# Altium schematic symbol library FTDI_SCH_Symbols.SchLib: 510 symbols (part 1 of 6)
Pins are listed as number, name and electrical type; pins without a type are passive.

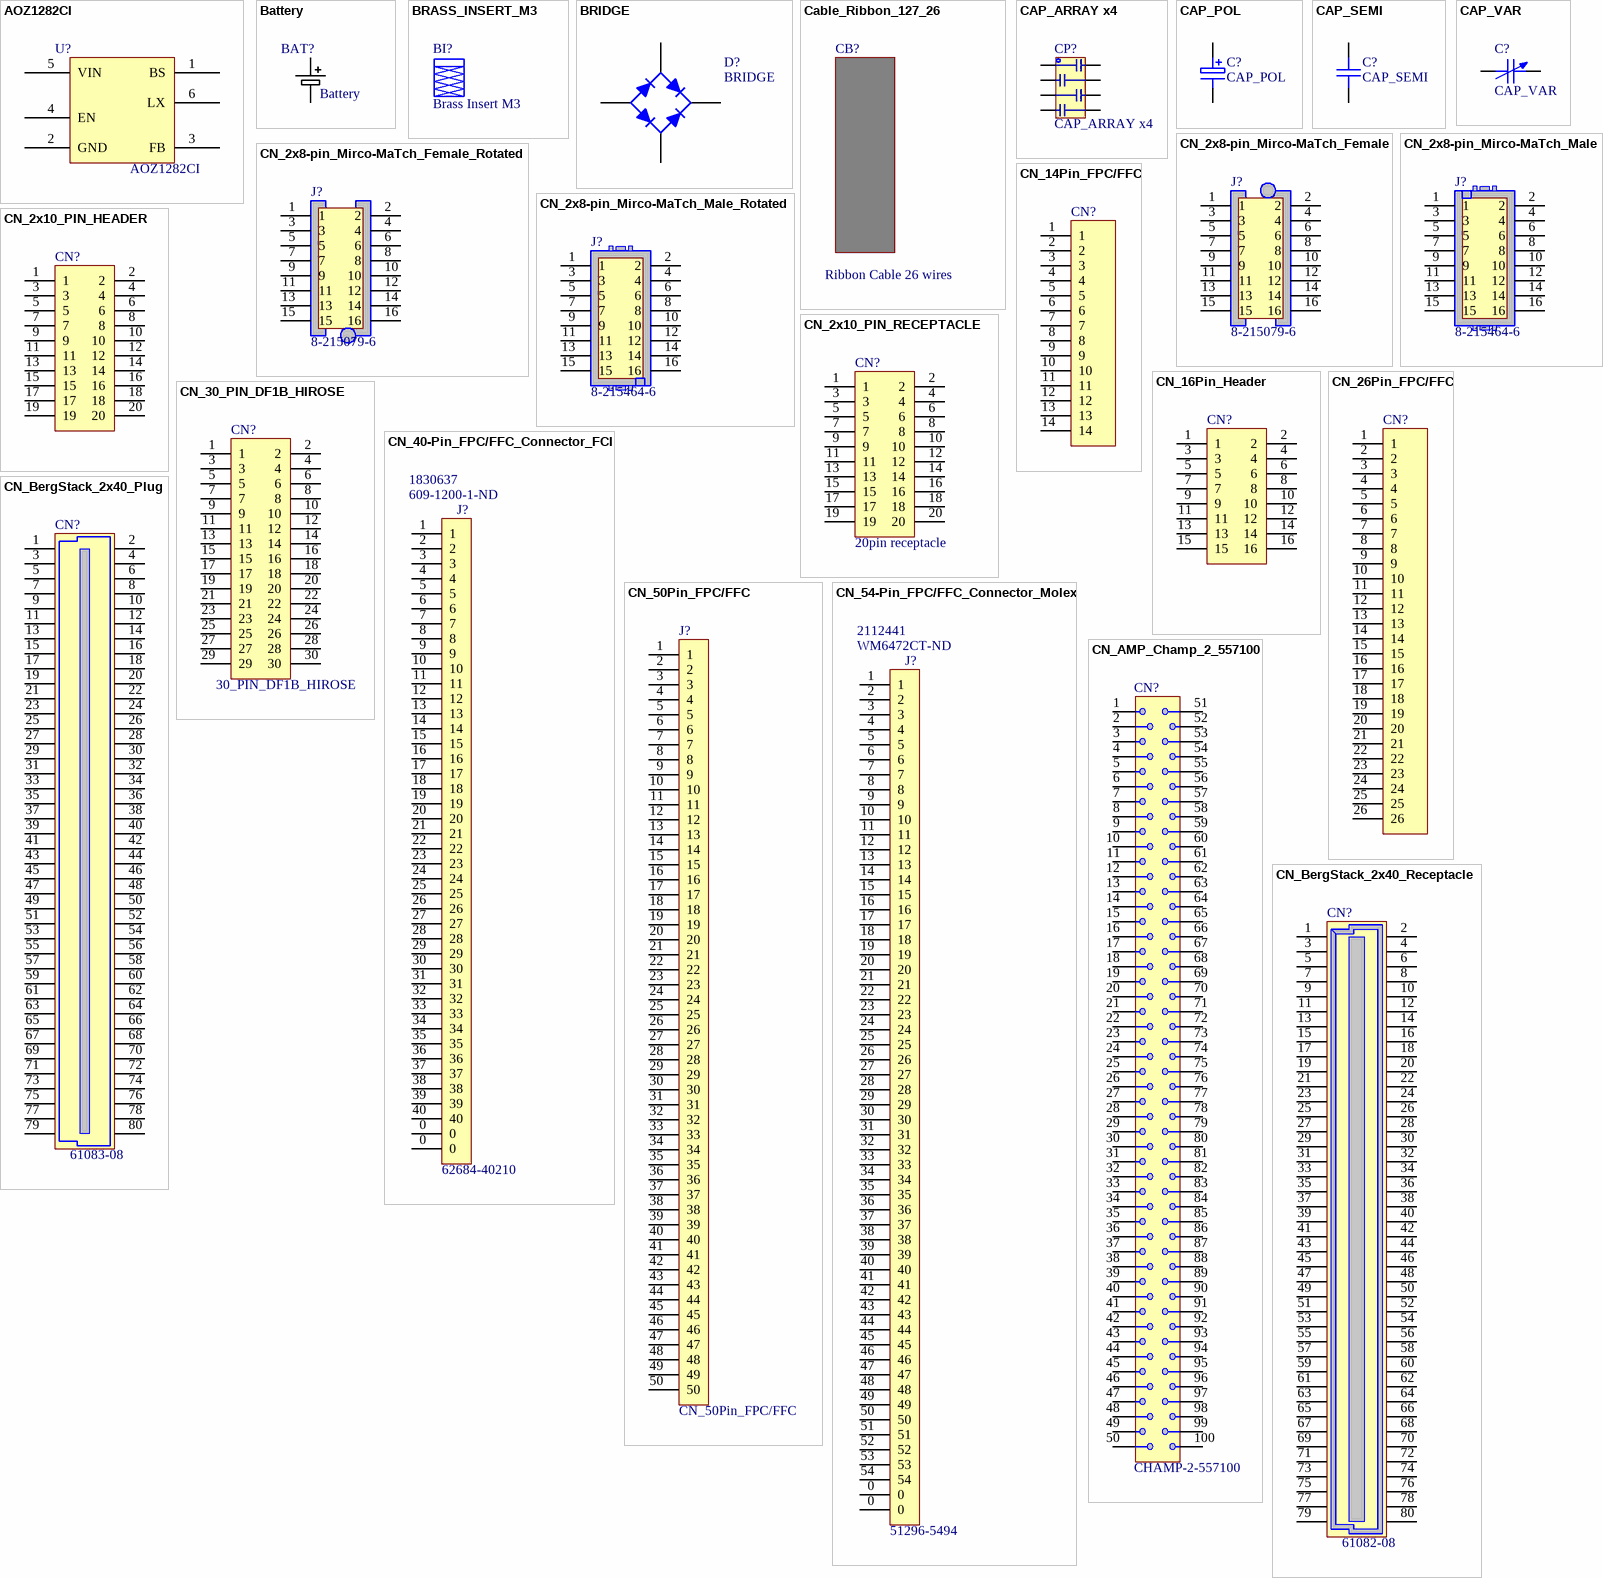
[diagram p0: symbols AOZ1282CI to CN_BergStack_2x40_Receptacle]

## AOZ1282CI
designator U?
pins: 1 BS, 2 GND, 3 FB, 4 EN, 5 VIN (power), 6 LX

## Battery
designator BAT?
pins: 1 +, 2 -

## BRASS_INSERT_M3
designator BI?, comment Brass Insert M3  (mechanical)

## BRIDGE
designator D?
Full Wave Diode Bridge
footprint D-38 (Bridge Rectifier; 4 Terminals; Body 9.4 x 9.4 mm (typ); Pitch 5.08 mm)
simulation model BRIDGE (Spice Subcircuit)
pins: 1 A, 2 C, 3 K, 4 C

## Cable_Ribbon_127_26
designator CB?, comment Ribbon Cable 26 wires  (mechanical)
Ribbon cable, 26-wires, 1.27mm pitch

## CAP_ARRAY x4
designator CP?
Capacitor array 3216 x 4
footprint MNR34 (3216x4 Resistor Array)
footprint RESARRAY-EXBV8V (EXBV8 Series Resistor Array, 4x0603, Isolated; Panasonic)
footprint RES_ARRAY_4X0603
pins: 1, 2, 3, 4, 5, 6, 7, 8

## CAP_POL
designator C?
Polarized Capacitor
simulation model CAP (Capacitor)
signal-integrity model Cap Pol
footprint CAPE-CASE A (Capacitor aluminium electrolitytic; SMT, Case A)
footprint CAPE-CASE B (Capacitor, aluminium electrolitytic; SMT, Case B)
footprint CAPE-4mm (Capacitor, aluminium electrolitytic; DIA 4mm; Pitch 1.5mm)
footprint CAPM-A-3216-18 (Capacitor, SMT Tantalum; Body 3.2 x 1.6 mm (LxW typ))
footprint CAPM-B-3528-21 (Capacitor, SMT Tantalum; Body 3.5 x 2.8 mm (LxW typ))
footprint CAPM-C-6032-28 (Capacitor, SMT, Tantalum; Body 6.0 x 3.2 mm (LxW typ))
footprint CAPM-D-7343-31 (Capacitor, SMT, Tantalum; Body 7.3 x 4.3 mm (LxW typ))
footprint CAPE-5mm (Capacitor, aluminium electrolitytic; DIA 5mm; Pitch 2mm)
footprint CAPE-6.3mm (Capacitor, aluminium electrolitytic; DIA 6,3mm; Pitch 2.5mm)
footprint CAPE-CASE C (Capacitor, aluminium electrolitytic; SMT, Case C)
pins: 1, 2
1 alternate drawing of the same symbol

## CAP_SEMI
designator C?
Capacitor bipolar
simulation model CAP (Semiconductor Capacitor)
signal-integrity model Cap Semi
footprint CAPC1608-0603 (Chip Capacitor; Body 1.6 x 0.8 mm (LxW typ))
footprint CAPC2012-0805 (Chip Capacitor; Body 2 x 1.3 mm (LxW typ))
footprint CAPC3216-1206 (Chip Capacitor; Body 3.2 x 1.6 mm (LxW typ))
footprint RAD-0.2 (Jumper Wire; 2 Leads)
pins: 1, 2

## CAP_VAR
designator C?
Variable or Adjustable Capacitor
signal-integrity model Cap Var
footprint MURATA-TZ03-TYPE-E (MURATA TRIMMER CAP TZ03 SERIES - E TYPE)
pins: 1, 2

## CN_2x8-pin_Mirco-MaTch_Female
designator J?, comment 8-215079-6
2x8-pin; Micro-MaTch; Female; On-Board Connector; TE Connectivity; 1-215079-6 (Reel Packaging) or 8-215079-6 (Box Packaging); Note: CONN FMALE-ON-BRD 16POS VERT T/H
footprint CN_16-Pin_Female_Micro-Match_1-215079-6 (Micro-MaTch Board-Board Receptacle; 16-possitions; 0.1"(2.54mm) pitch; staggered pins; TE Connectivity; 1-215079-6 (8-215079-6))
pins: 1, 2, 3, 4, 5, 6, 7, 8, 9, 10, 11, 12, 13, 14, 15, 16

## CN_2x8-pin_Mirco-MaTch_Female_Rotated
designator J?, comment 8-215079-6
2x8-pin; Micro-MaTch; Female; On-Board Connector; TE Connectivity; 1-215079-6 (Reel Packaging) or 8-215079-6 (Box Packaging); Note: CONN FMALE-ON-BRD 16POS VERT T/H
footprint CN_16-Pin_Female_Micro-Match_1-215079-6-Rotated_180_deg (Micro-MaTch Board-Board Receptacle; 16-possitions; 0.1"(2.54mm) pitch; staggered pins; TE Connectivity; 1-215079-6 (8-215079-6))
pins: 1, 2, 3, 4, 5, 6, 7, 8, 9, 10, 11, 12, 13, 14, 15, 16

## CN_2x8-pin_Mirco-MaTch_Male
designator J?, comment 8-215464-6
2x8-pin; Micro-MaTch; Male; On-Board Connector; TE Connectivity; 1-215464-6 (Reel packaging) or 8-215464-6 (Box Packaging); Note: CONN HEADER 16POS VERT DL TIN
footprint CN_16-Pins_Female_Micro-Match_8-215079-6 (Micro-MaTch Board-Board Receptacle; 16-possitions; 0.1"(2.54mm) pitch; staggered pins)
pins: 1, 2, 3, 4, 5, 6, 7, 8, 9, 10, 11, 12, 13, 14, 15, 16

## CN_2x8-pin_Mirco-MaTch_Male_Rotated
designator J?, comment 8-215464-6
2x8-pin; Micro-MaTch; Male; On-Board Connector; TE Connectivity; 1-215464-6 (Reel packaging) or 8-215464-6 (Box Packaging); Note: CONN HEADER 16POS VERT DL TIN
footprint CN_16-Pin_Male_Micro-Match_1-215464-6 - rotated (Micro-MaTch Board-Board Header; 16-possitions; 0.1"(2.54mm) pitch; staggered pins; TE Connectivity; 1-215464-6 (8-215464-6))
pins: 1, 2, 3, 4, 5, 6, 7, 8, 9, 10, 11, 12, 13, 14, 15, 16

## CN_2x10_PIN_HEADER
designator CN?
footprint CN_20_Pin_Socket
pins: 1, 2, 3, 4, 5, 6, 7, 8, 9, 10, 11, 12, 13, 14, 15, 16, 17, 18, 19, 20

## CN_2x10_PIN_RECEPTACLE
designator CN?, comment 20pin receptacle
Receptacle; 20 pin
footprint CN_20_Pin_Receptacle
pins: 1, 2, 3, 4, 5, 6, 7, 8, 9, 10, 11, 12, 13, 14, 15, 16, 17, 18, 19, 20

## CN_14Pin_FPC/FFC
designator CN?
footprint CN_16Pin_Female_Header (Dual Row; Vertical; 0.1" (2.54mm); Female Header)
footprint CN_FCI_SFW14R-1ST (FPC/FFC Connector; SFW14R-1ST; 14 Positions; 1.0mm Spaced Bottom Contact; FCI)
pins: 1, 2, 3, 4, 5, 6, 7, 8, 9, 10, 11, 12, 13, 14, 15 0 hidden, 16 0 hidden

## CN_16Pin_Header
designator CN?
footprint CN_16Pin_Female_Header (Dual Row; Vertical; 0.1" (2.54mm); Female Header)
footprint CN_16Pin_Male_Header (Dual Row; Vertical; 0.1" (2.54mm); Male Header)
pins: 1, 2, 3, 4, 5, 6, 7, 8, 9, 10, 11, 12, 13, 14, 15, 16

## CN_26Pin_FPC/FFC
designator CN?
footprint CN_16Pin_Female_Header (Dual Row; Vertical; 0.1" (2.54mm); Female Header)
footprint CN_FCI_SFW26R-1ST (FPC/FFC Connector; SFW26R-1ST; 26 Positions; 1.0mm Spaced Bottom Contact; FCI)
pins: 1, 2, 3, 4, 5, 6, 7, 8, 9, 10, 11, 12, 13, 14, 15, 16, 17, 18, 19, 20, 21, 22, 23, 24, 25, 26, 27 0 hidden, 28 0 hidden

## CN_30_PIN_DF1B_HIROSE
designator CN?, comment 30_PIN_DF1B_HIROSE
Hirose, DF1B Series, 2.5mm Pitch Connector for Discrete Wire Connection
footprint CN_DF1B-30DP-2.5DS (Hirose Double Row Right Angle Pin Header, 2.5mm pitch, Catalog number - 541-0642-4-**)
pins: 1, 2, 3, 4, 5, 6, 7, 8, 9, 10, 11, 12, 13, 14, 15, 16, 17, 18, 19, 20, 21, 22, 23, 24, 25, 26, 27, 28, 29, 30

## CN_40-Pin_FPC/FFC_Connector_FCI
designator J?, comment 62684-40210  Supplier Part Number 1: 609-1200-1-ND  Supplier Part Number 2: 1830637
40-Pin; 0.5mm pitch; FPC/FFC Connector; Top Contacts; FCI; Part No. 62684-40210
footprint CN_4-5nch_TFT (Connector for 4.3 and 5" touch screens)
pins: 0, 0, 1, 2, 3, 4, 5, 6, 7, 8, 9, 10, 11, 12, 13, 14, 15, 16, 17, 18, 19, 20, 21, 22, 23, 24, 25, 26, 27, 28, 29, 30, 31, 32, 33, 34, 35, 36, 37, 38, 39, 40

## CN_50Pin_FPC/FFC
designator J?
footprint CN_50Pin_FPC/FFC
pins: 1, 2, 3, 4, 5, 6, 7, 8, 9, 10, 11, 12, 13, 14, 15, 16, 17, 18, 19, 20, 21, 22, 23, 24, 25, 26, 27, 28, 29, 30, 31, 32, 33, 34, 35, 36, 37, 38, 39, 40, 41, 42, 43, 44, 45, 46, 47, 48, 49, 50

## CN_54-Pin_FPC/FFC_Connector_Molex
designator J?, comment 51296-5494  Supplier Part Number 1: WM6472CT-ND  Supplier Part Number 2: 2112441
54-Pin; 0.5mm pitch; FPC/FFC Connector; Bottom Contacts; Molex; Part No. 51296-5494; Manufacturer: Molex Inc; ManufacturerPartNo: 0512965494; Note: CONN FFC/FPC 54POS ZIF .5MM SMD
footprint CN_3-5nch_TFT (Connector for 3.5" touch screens)
pins: 0, 0, 1, 2, 3, 4, 5, 6, 7, 8, 9, 10, 11, 12, 13, 14, 15, 16, 17, 18, 19, 20, 21, 22, 23, 24, 25, 26, 27, 28, 29, 30, 31, 32, 33, 34, 35, 36, 37, 38, 39, 40, 41, 42, 43, 44, 45, 46, 47, 48, 49, 50, 51, 52, 53, 54

## CN_AMP_Champ_2_557100
designator CN?, comment CHAMP-2-557100
Amp Champ-2 series 100 pin connector
footprint CN_CHAMP-100 (Connector; CHAMP Miniature Ribbon 050 Series I; 100 Position; Right Angle)
pins: 1, 2, 3, 4, 5, 6, 7, 8, 9, 10, 11, 12, 13, 14, 15, 16, 17, 18, 19, 20, 21, 22, 23, 24, 25, 26, 27, 28, 29, 30, 31, 32, 33, 34, 35, 36, 37, 38, 39, 40, 41, 42, 43, 44, 45, 46, 47, 48, 49, 50, 51, 52, 53, 54, 55, 56, 57, 58, 59, 60, 61, 62, 63, 64, 65, 66, 67, 68, 69, 70, 71, 72, 73, 74, 75, 76, 77, 78, 79, 80, 81, 82, 83, 84, 85, 86, 87, 88, 89, 90, 91, 92, 93, 94, 95, 96, 97, 98, 99, 100

## CN_BergStack_2x40_Plug
designator CN?, comment 61083-08
FCI, BesrgStack family, 2x40 pins, 0.8mm pitch, Board to Board Plug
footprint CN_61083-084402LF (FCI, 2x40 pins, 0.8mm pitch, 7.7mm height, Board to Board Plug)
pins: 1, 2, 3, 4, 5, 6, 7, 8, 9, 10, 11, 12, 13, 14, 15, 16, 17, 18, 19, 20, 21, 22, 23, 24, 25, 26, 27, 28, 29, 30, 31, 32, 33, 34, 35, 36, 37, 38, 39, 40, 41, 42, 43, 44, 45, 46, 47, 48, 49, 50, 51, 52, 53, 54, 55, 56, 57, 58, 59, 60, 61, 62, 63, 64, 65, 66, 67, 68, 69, 70, 71, 72, 73, 74, 75, 76, 77, 78, 79, 80

## CN_BergStack_2x40_Receptacle
designator CN?, comment 61082-08
FCI, BesrgStack family, 2x40 pins, 0.8mm pitch, Board to Board Receptacle
footprint CN_61082-082402LF (FCI, 2x40 pins, 0.8mm pitch, 7.7mm height, Board to Board Receptacle)
pins: 1, 2, 3, 4, 5, 6, 7, 8, 9, 10, 11, 12, 13, 14, 15, 16, 17, 18, 19, 20, 21, 22, 23, 24, 25, 26, 27, 28, 29, 30, 31, 32, 33, 34, 35, 36, 37, 38, 39, 40, 41, 42, 43, 44, 45, 46, 47, 48, 49, 50, 51, 52, 53, 54, 55, 56, 57, 58, 59, 60, 61, 62, 63, 64, 65, 66, 67, 68, 69, 70, 71, 72, 73, 74, 75, 76, 77, 78, 79, 80

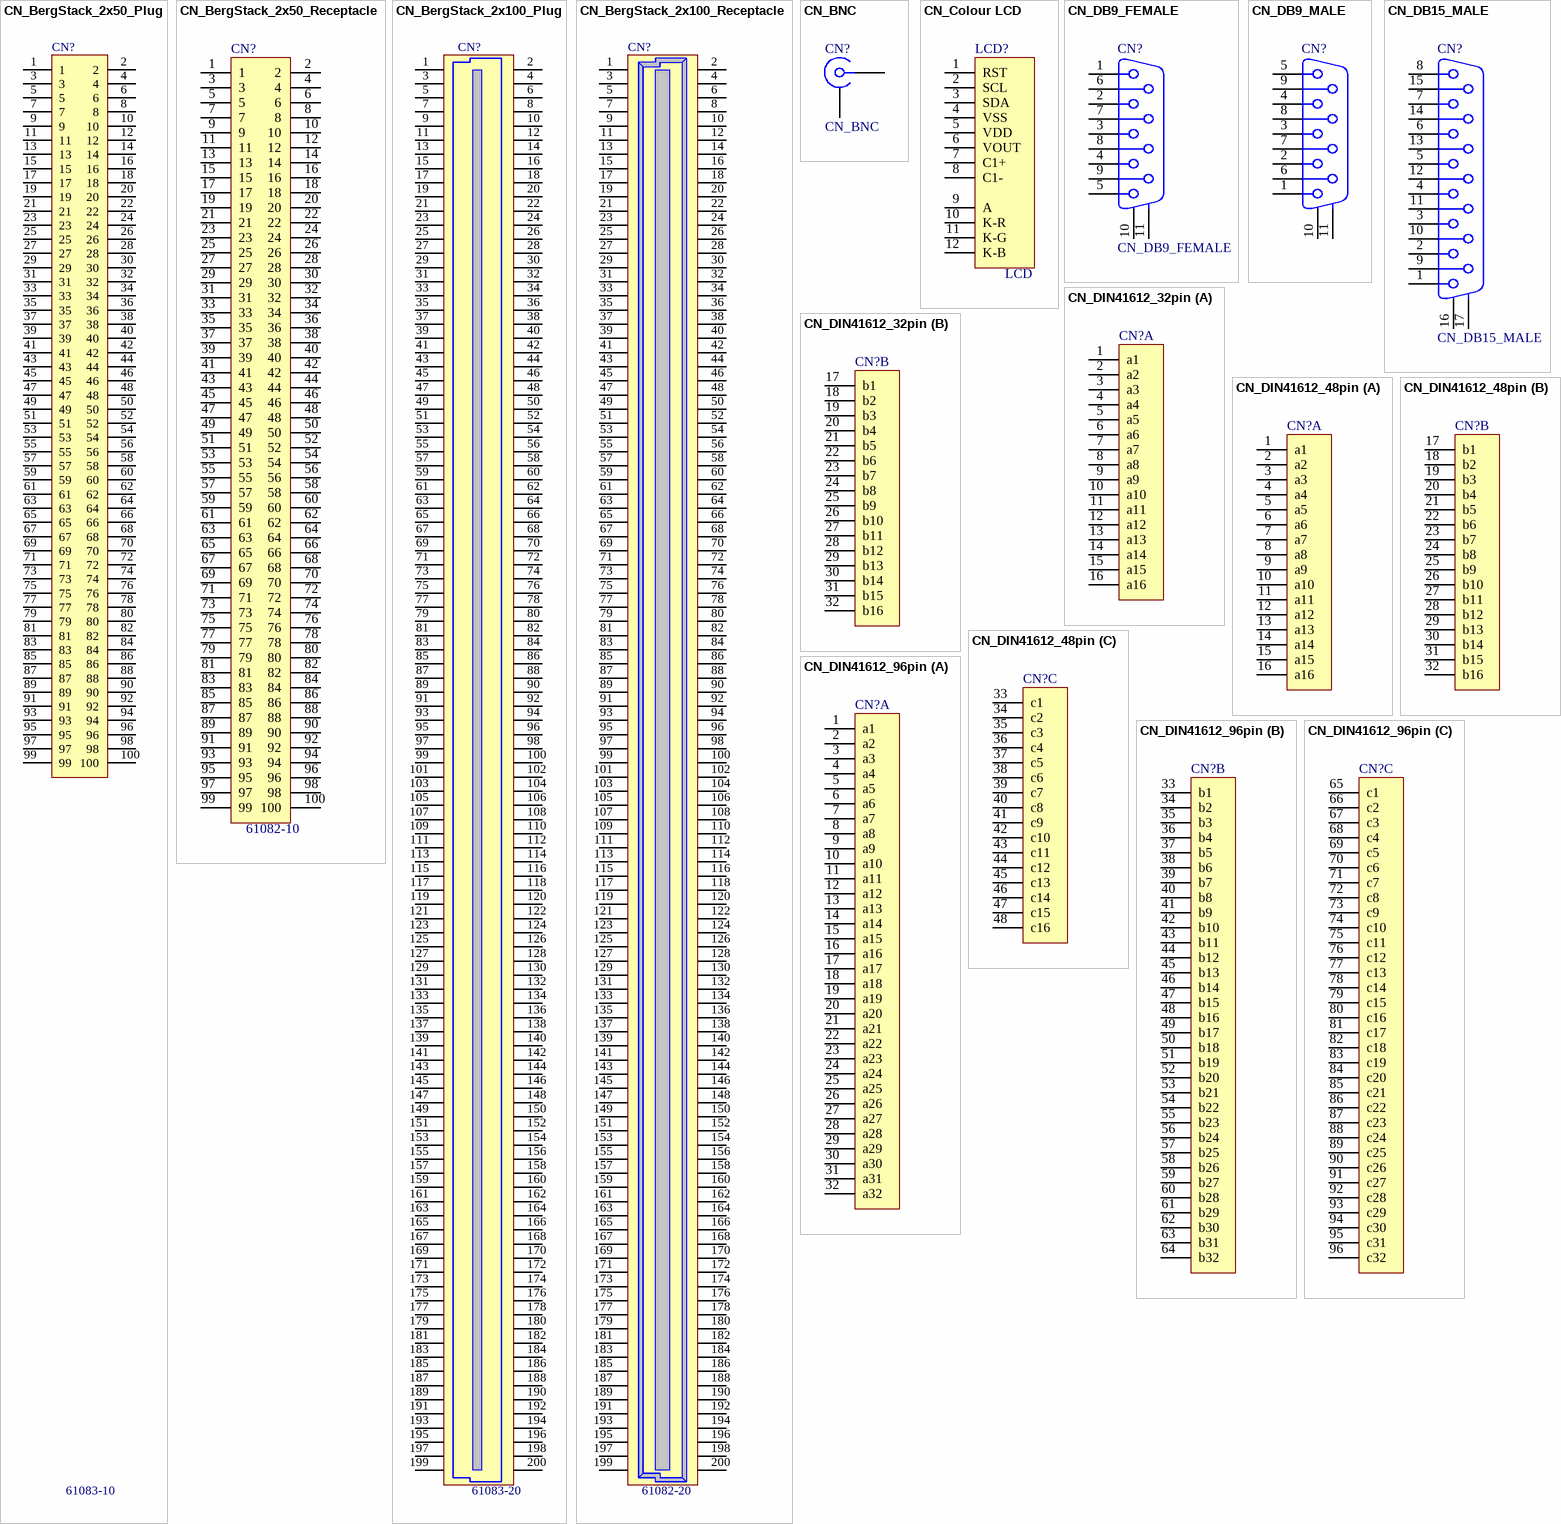
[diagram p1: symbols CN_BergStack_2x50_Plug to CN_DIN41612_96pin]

## CN_BergStack_2x50_Plug
designator CN?, comment 61083-10
FCI, BesrgStack family, 2x50 pins, 0.8mm pitch, Board to Board Plug
footprint CN_61083-104402LF (FCI, 2x50 pins, 0.8mm pitch, 7.7mm height, Board to Board Plug)
pins: 1, 2, 3, 4, 5, 6, 7, 8, 9, 10, 11, 12, 13, 14, 15, 16, 17, 18, 19, 20, 21, 22, 23, 24, 25, 26, 27, 28, 29, 30, 31, 32, 33, 34, 35, 36, 37, 38, 39, 40, 41, 42, 43, 44, 45, 46, 47, 48, 49, 50, 51, 52, 53, 54, 55, 56, 57, 58, 59, 60, 61, 62, 63, 64, 65, 66, 67, 68, 69, 70, 71, 72, 73, 74, 75, 76, 77, 78, 79, 80, 81, 82, 83, 84, 85, 86, 87, 88, 89, 90, 91, 92, 93, 94, 95, 96, 97, 98, 99, 100

## CN_BergStack_2x50_Receptacle
designator CN?, comment 61082-10
FCI, BesrgStack family, 2x50 pins, 0.8mm pitch, Board to Board Receptacle
footprint CN_61082-102402LF - duplicate (FCI, 2x50 pins, 0.8mm pitch, 7.7mm height, Board to Board Receptacle)
pins: 1, 2, 3, 4, 5, 6, 7, 8, 9, 10, 11, 12, 13, 14, 15, 16, 17, 18, 19, 20, 21, 22, 23, 24, 25, 26, 27, 28, 29, 30, 31, 32, 33, 34, 35, 36, 37, 38, 39, 40, 41, 42, 43, 44, 45, 46, 47, 48, 49, 50, 51, 52, 53, 54, 55, 56, 57, 58, 59, 60, 61, 62, 63, 64, 65, 66, 67, 68, 69, 70, 71, 72, 73, 74, 75, 76, 77, 78, 79, 80, 81, 82, 83, 84, 85, 86, 87, 88, 89, 90, 91, 92, 93, 94, 95, 96, 97, 98, 99, 100

## CN_BergStack_2x100_Plug
designator CN?, comment 61083-20
FCI, BesrgStack family, 2x100 pins, 0.8mm pitch, Board to Board Plug
footprint CN_61083-204402LF (FCI, 2x100 pins, 0.8mm pitch, 7.7mm height, Board to Board Plug)
pins: 1, 2, 3, 4, 5, 6, 7, 8, 9, 10, 11, 12, 13, 14, 15, 16, 17, 18, 19, 20, 21, 22, 23, 24, 25, 26, 27, 28, 29, 30, 31, 32, 33, 34, 35, 36, 37, 38, 39, 40, 41, 42, 43, 44, 45, 46, 47, 48, 49, 50, 51, 52, 53, 54, 55, 56, 57, 58, 59, 60, 61, 62, 63, 64, 65, 66, 67, 68, 69, 70, 71, 72, 73, 74, 75, 76, 77, 78, 79, 80, 81, 82, 83, 84, 85, 86, 87, 88, 89, 90, 91, 92, 93, 94, 95, 96, 97, 98, 99, 100, 101, 102, 103, 104, 105, 106, 107, 108, 109, 110, 111, 112, 113, 114, 115, 116, 117, 118, 119, 120, 121, 122, 123, 124, 125, 126, 127, 128, 129, 130, 131, 132, 133, 134, 135, 136, 137, 138, 139, 140, 141, 142, 143, 144, 145, 146, 147, 148, 149, 150, 151, 152, 153, 154, 155, 156, 157, 158, 159, 160, 161, 162, 163, 164, 165, 166, 167, 168, 169, 170, 171, 172, 173, 174, 175, 176, 177, 178, 179, 180, 181, 182, 183, 184, 185, 186, 187, 188, 189, 190, 191, 192, 193, 194, 195, 196, 197, 198, 199, 200

## CN_BergStack_2x100_Receptacle
designator CN?, comment 61082-20
FCI, BesrgStack family, 2x100 pins, 0.8mm pitch, Board to Board Receptacle
footprint CN_61082-202402LF (FCI, 2x100 pins, 0.8mm pitch, 7.7mm height, Board to Board Receptacle)
pins: 1, 2, 3, 4, 5, 6, 7, 8, 9, 10, 11, 12, 13, 14, 15, 16, 17, 18, 19, 20, 21, 22, 23, 24, 25, 26, 27, 28, 29, 30, 31, 32, 33, 34, 35, 36, 37, 38, 39, 40, 41, 42, 43, 44, 45, 46, 47, 48, 49, 50, 51, 52, 53, 54, 55, 56, 57, 58, 59, 60, 61, 62, 63, 64, 65, 66, 67, 68, 69, 70, 71, 72, 73, 74, 75, 76, 77, 78, 79, 80, 81, 82, 83, 84, 85, 86, 87, 88, 89, 90, 91, 92, 93, 94, 95, 96, 97, 98, 99, 100, 101, 102, 103, 104, 105, 106, 107, 108, 109, 110, 111, 112, 113, 114, 115, 116, 117, 118, 119, 120, 121, 122, 123, 124, 125, 126, 127, 128, 129, 130, 131, 132, 133, 134, 135, 136, 137, 138, 139, 140, 141, 142, 143, 144, 145, 146, 147, 148, 149, 150, 151, 152, 153, 154, 155, 156, 157, 158, 159, 160, 161, 162, 163, 164, 165, 166, 167, 168, 169, 170, 171, 172, 173, 174, 175, 176, 177, 178, 179, 180, 181, 182, 183, 184, 185, 186, 187, 188, 189, 190, 191, 192, 193, 194, 195, 196, 197, 198, 199, 200

## CN_BNC
designator CN?
footprint CN_BNC/RA
pins: 1, 2

## CN_Colour LCD
designator LCD?, comment LCD
Header, -Pin; Manufacturer: Newhaven Display Intl; ManufacturerPartNo: NHD-C0220BIZ-FS(RGB)-FBW-3VM-ND; Note: LCD DISPLAY RGB LED BKLT 20 X 2
footprint Colour LCD
signal-integrity model Connector
pins: 1 RST, 2 SCL, 3 SDA, 4 VSS, 5 VDD, 6 VOUT, 7 C1+, 8 C1-, 9 A, 10 K-R, 11 K-G, 12 K-B

## CN_DB9_FEMALE
designator CN?
Connector; D-Sub; 9 pin; Female
signal-integrity model Connector
footprint CN_DSUB-9_FEMALE (Connector; D Subminiature AMPLIMITE 2000; 9 Position; Right Angle)
pins: 1, 2, 3, 4, 5, 6, 7, 8, 9, 10 MH1, 11 MH2

## CN_DB9_MALE
designator CN?
Connector D-Sub; 9 Position; Male
signal-integrity model Connector
footprint CN_DSUB-9_MALE (Connector; D Subminiature AMPLIMITE 2000; 9 Position; Right Angle)
pins: 1, 2, 3, 4, 5, 6, 7, 8, 9, 10 MH1, 11 MH2

## CN_DB15_MALE
designator CN?
Socket; D-Sub;, 15 Position, Right Angle; Male
signal-integrity model Connector
footprint CN_DSUB-15_MALE (Connector; D Subminiature AMPLIMITE 2000; 15 Position; Right Angle)
pins: 1, 2, 3, 4, 5, 6, 7, 8, 9, 10, 11, 12, 13, 14, 15, 16 MH1, 17 MH2

## CN_DIN41612_32pin
designator CN?
footprint CN_DIN41612_32Pin_Female (Connector DIN41612; 32 pin; Female; horizontal)
part A pins: 1 a1, 2 a2, 3 a3, 4 a4, 5 a5, 6 a6, 7 a7, 8 a8, 9 a9, 10 a10, 11 a11, 12 a12, 13 a13, 14 a14, 15 a15, 16 a16
part B pins: 17 b1, 18 b2, 19 b3, 20 b4, 21 b5, 22 b6, 23 b7, 24 b8, 25 b9, 26 b10, 27 b11, 28 b12, 29 b13, 30 b14, 31 b15, 32 b16

## CN_DIN41612_48pin
designator CN?
footprint CN_DIN41612_48 pin Male (DIN41612 series; Harting Part No. 09 28 148 6903 ; Number of Positions = 48; pitch 2.54 mm)
part A pins: 1 a1, 2 a2, 3 a3, 4 a4, 5 a5, 6 a6, 7 a7, 8 a8, 9 a9, 10 a10, 11 a11, 12 a12, 13 a13, 14 a14, 15 a15, 16 a16
part B pins: 17 b1, 18 b2, 19 b3, 20 b4, 21 b5, 22 b6, 23 b7, 24 b8, 25 b9, 26 b10, 27 b11, 28 b12, 29 b13, 30 b14, 31 b15, 32 b16
part C pins: 33 c1, 34 c2, 35 c3, 36 c4, 37 c5, 38 c6, 39 c7, 40 c8, 41 c9, 42 c10, 43 c11, 44 c12, 45 c13, 46 c14, 47 c15, 48 c16

## CN_DIN41612_96pin
designator CN?
footprint CN_DIN41612_96 pin Male (DIN41612 series; FCI Part No. 86093967113745E1LF; Number of Positions = 95; pitch 2.54 mm)
part A pins: 1 a1, 2 a2, 3 a3, 4 a4, 5 a5, 6 a6, 7 a7, 8 a8, 9 a9, 10 a10, 11 a11, 12 a12, 13 a13, 14 a14, 15 a15, 16 a16, 17 a17, 18 a18, 19 a19, 20 a20, 21 a21, 22 a22, 23 a23, 24 a24, 25 a25, 26 a26, 27 a27, 28 a28, 29 a29, 30 a30, 31 a31, 32 a32
part B pins: 33 b1, 34 b2, 35 b3, 36 b4, 37 b5, 38 b6, 39 b7, 40 b8, 41 b9, 42 b10, 43 b11, 44 b12, 45 b13, 46 b14, 47 b15, 48 b16, 49 b17, 50 b18, 51 b19, 52 b20, 53 b21, 54 b22, 55 b23, 56 b24, 57 b25, 58 b26, 59 b27, 60 b28, 61 b29, 62 b30, 63 b31, 64 b32
part C pins: 65 c1, 66 c2, 67 c3, 68 c4, 69 c5, 70 c6, 71 c7, 72 c8, 73 c9, 74 c10, 75 c11, 76 c12, 77 c13, 78 c14, 79 c15, 80 c16, 81 c17, 82 c18, 83 c19, 84 c20, 85 c21, 86 c22, 87 c23, 88 c24, 89 c25, 90 c26, 91 c27, 92 c28, 93 c29, 94 c30, 95 c31, 96 c32

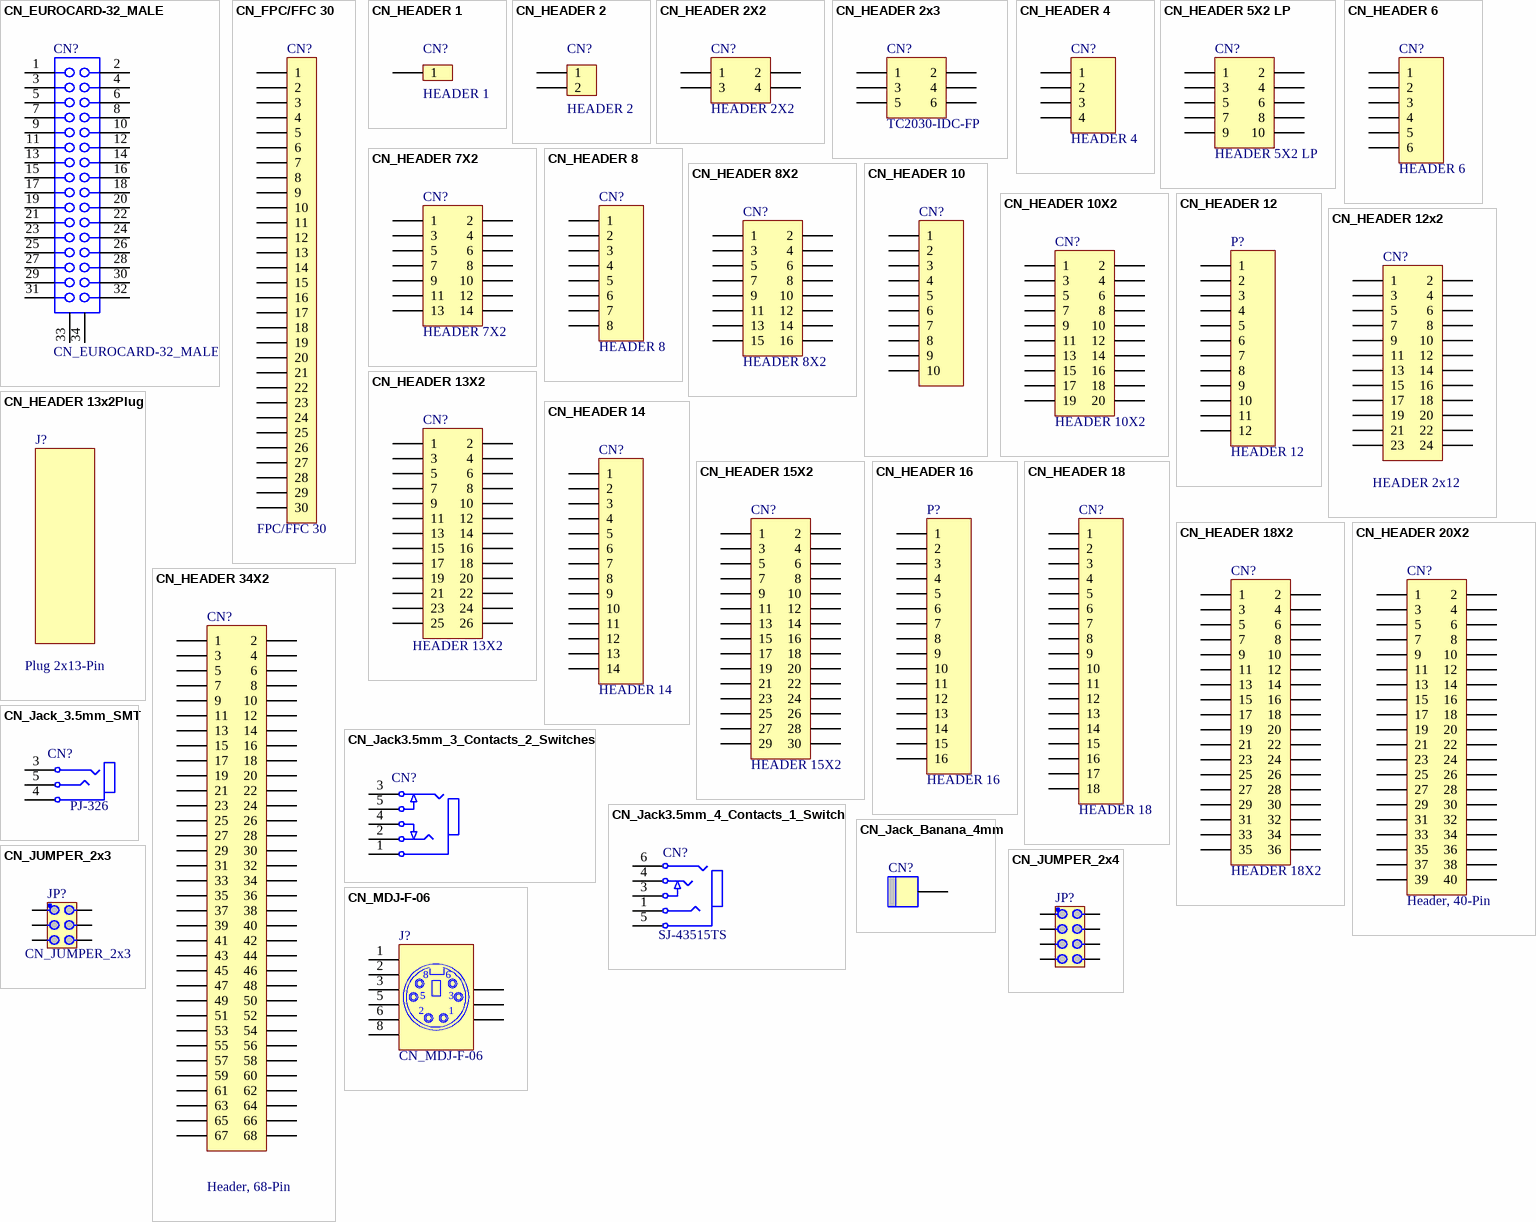
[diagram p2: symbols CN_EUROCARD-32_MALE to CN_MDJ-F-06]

## CN_EUROCARD-32_MALE
designator CN?
Eurocard DIN 41612, Type 2Q, Half Size, 32 Position, Rows a+b, Performance level 2, Female, Lead 3.0 mm, Pitch 2.54 mm
signal-integrity model DIN 41612
footprint CN_DIN-32_HARTING (Connector; DIN 41612, Type Q, Thru-Hole; Rows a+b, 32 Position; Right Angle)
pins: 1, 2, 3, 4, 5, 6, 7, 8, 9, 10, 11, 12, 13, 14, 15, 16, 17, 18, 19, 20, 21, 22, 23, 24, 25, 26, 27, 28, 29, 30, 31, 32, 33 MH1 "Mounting Fixture", 34 MH2 "Mounting Fixture"

## CN_FPC/FFC 30
designator CN?, comment FPC/FFC 30
Header, 15-Pin, Dual row
signal-integrity model Connector
footprint CN_BL112-30RL (FPC/FFC Connector, 30 pins, 0.5mm pitch, Suncagey)
pins: 1, 2, 3, 4, 5, 6, 7, 8, 9, 10, 11, 12, 13, 14, 15, 16, 17, 18, 19, 20, 21, 22, 23, 24, 25, 26, 27, 28, 29, 30

## CN_HEADER 1
designator CN?, comment HEADER 1
Header, -Pin
footprint HDR1X6 (Connector; Header; 6 Position)
signal-integrity model Connector
pins: 1

## CN_HEADER 2
designator CN?, comment HEADER 2
Header, 2-Pin
footprint HDR1X6 (Connector; Header; 6 Position)
signal-integrity model Connector
pins: 1, 2

## CN_HEADER 2X2
designator CN?, comment HEADER 2X2
Low profile header, 4-Pin, Dual row, pitch 0.1"
signal-integrity model Connector
pins: 1, 2, 3, 4

## CN_HEADER 2x3
designator CN?, comment TC2030-IDC-FP
ISP Connector, 6-Pin, Dual row, pitch 0.05"; Tag-Connect; TC2030-IDC-FP
signal-integrity model Connector
footprint CN_TC2030-IDC_6-pin_ISP_Connector (TC2030-IDC-10 6-Pin Tag-Connect Plug-of-Nails(tm) Legged Spring-Pin Cable with Ribbon)
pins: 1, 2, 3, 4, 5, 6

## CN_HEADER 4
designator CN?, comment HEADER 4
Header, 4-Pin
footprint HDR1X6 (Connector; Header; 6 Position)
signal-integrity model Connector
pins: 1, 2, 3, 4

## CN_HEADER 5X2 LP
designator CN?, comment HEADER 5X2 LP
Low profile header for IDC socket, 5-Pin, Dual row, pitch 0.1"
signal-integrity model Connector
footprint HDR2X5LP (Connector; Header; Lo Profile; 5x2 Position; Pitch 0.1")
pins: 1, 2, 3, 4, 5, 6, 7, 8, 9, 10

## CN_HEADER 6
designator CN?, comment HEADER 6
Header, 6-Pin
footprint HDR1X6 (Connector; Header; 6 Position)
signal-integrity model Connector
pins: 1, 2, 3, 4, 5, 6

## CN_HEADER 7X2
designator CN?, comment HEADER 7X2
Header, 2x7-Pin
footprint CN_HDR2X7 (Connector; Header; 7x2 Position; pitch 0.1")
signal-integrity model Connector
pins: 1, 2, 3, 4, 5, 6, 7, 8, 9, 10, 11, 12, 13, 14

## CN_HEADER 8
designator CN?, comment HEADER 8
Header, 8-Pin
footprint HDR1X8 (Connector; Header; 8 Position)
signal-integrity model Connector
pins: 1, 2, 3, 4, 5, 6, 7, 8

## CN_HEADER 8X2
designator CN?, comment HEADER 8X2
Header, 8-Pin, Dual row
footprint HDR2X8 (Connector; Header; 8x2 Position)
signal-integrity model Connector
pins: 1, 2, 3, 4, 5, 6, 7, 8, 9, 10, 11, 12, 13, 14, 15, 16

## CN_HEADER 10
designator CN?
Header, 10-Pin
footprint CN_HDR1X10 (Connector; Header; 10 Position; pitch 0.1")
signal-integrity model Connector
pins: 1, 2, 3, 4, 5, 6, 7, 8, 9, 10

## CN_HEADER 10X2
designator CN?, comment HEADER 10X2
Header, 9-Pin, Dual row
footprint CN_HDR2X10_2mm (Connector; Header; 2 Rows x 10 Positions; pitch 2.0mm)
signal-integrity model Connector
pins: 1, 2, 3, 4, 5, 6, 7, 8, 9, 10, 11, 12, 13, 14, 15, 16, 17, 18, 19, 20

## CN_HEADER 12
designator P?, comment HEADER 12
Header, 12-Pin
footprint HDR1X12 (Connector; Header; 12 Position)
signal-integrity model Connector
pins: 1, 2, 3, 4, 5, 6, 7, 8, 9, 10, 11, 12

## CN_HEADER 12x2
designator CN?, comment HEADER 2x12
Header, 2x12-Pin, 0.1" pitch
signal-integrity model Connector
footprint CN_HDR2X12 LP (Connector; Header; Vertical; Low Profile; 2x12 Positions; Pitch 0.1")
pins: 1, 2, 3, 4, 5, 6, 7, 8, 9, 10, 11, 12, 13, 14, 15, 16, 17, 18, 19, 20, 21, 22, 23, 24

## CN_HEADER 13X2
designator CN?, comment HEADER 13X2
Header, 2x13-Pin, 0.1" pitch
signal-integrity model Connector
footprint CN_HDRM2X13 (Connector; Header; Male; 13x2 Position; Pitch 0.1")
pins: 1, 2, 3, 4, 5, 6, 7, 8, 9, 10, 11, 12, 13, 14, 15, 16, 17, 18, 19, 20, 21, 22, 23, 24, 25, 26

## CN_HEADER 13x2Plug
designator J?, comment Plug 2x13-Pin  (mechanical)
Plug, 2x13-Pin, 0.1" pitch

## CN_HEADER 14
designator CN?, comment HEADER 14
Header, 14-Pin
footprint HDR1X14 (Connector; Header; 14 Position)
signal-integrity model Connector
pins: 1, 2, 3, 4, 5, 6, 7, 8, 9, 10, 11, 12, 13, 14

## CN_HEADER 15X2
designator CN?, comment HEADER 15X2
Header, 15-Pin, Dual row
signal-integrity model Connector
footprint CN_HDR2X15 (Connector; Header; Female; 15x2 Position; Pitch 0.1")
pins: 1, 2, 3, 4, 5, 6, 7, 8, 9, 10, 11, 12, 13, 14, 15, 16, 17, 18, 19, 20, 21, 22, 23, 24, 25, 26, 27, 28, 29, 30

## CN_HEADER 16
designator P?, comment HEADER 16
Header, 16-Pin
footprint HDR1X16 (Connector; Header; 16 Position)
signal-integrity model Connector
pins: 1, 2, 3, 4, 5, 6, 7, 8, 9, 10, 11, 12, 13, 14, 15, 16

## CN_HEADER 18
designator CN?, comment HEADER 18
Header, 18-Pin
footprint HDR1X16 (Connector; Header; 16 Position)
signal-integrity model Connector
pins: 1, 2, 3, 4, 5, 6, 7, 8, 9, 10, 11, 12, 13, 14, 15, 16, 17, 18

## CN_HEADER 18X2
designator CN?, comment HEADER 18X2
Header, 18-Pin, Dual row
footprint HDR2X18 (Connector; Header; 18x2 Position)
signal-integrity model Connector
pins: 1, 2, 3, 4, 5, 6, 7, 8, 9, 10, 11, 12, 13, 14, 15, 16, 17, 18, 19, 20, 21, 22, 23, 24, 25, 26, 27, 28, 29, 30, 31, 32, 33, 34, 35, 36

## CN_HEADER 20X2
designator CN?, comment Header, 40-Pin
Header, 40-Pin, Dual row
footprint CN_HDR2X20 (Connector; Header; Male; 2x20 Positions; Pitch 0.1")
signal-integrity model Connector
pins: 1, 2, 3, 4, 5, 6, 7, 8, 9, 10, 11, 12, 13, 14, 15, 16, 17, 18, 19, 20, 21, 22, 23, 24, 25, 26, 27, 28, 29, 30, 31, 32, 33, 34, 35, 36, 37, 38, 39, 40

## CN_HEADER 34X2
designator CN?, comment Header, 68-Pin
Header, 68-Pin, Dual row
footprint CN_HDR2X34 (Connector; Header; Male; 2x34 Positions; Pitch 0.1")
signal-integrity model Connector
pins: 1, 2, 3, 4, 5, 6, 7, 8, 9, 10, 11, 12, 13, 14, 15, 16, 17, 18, 19, 20, 21, 22, 23, 24, 25, 26, 27, 28, 29, 30, 31, 32, 33, 34, 35, 36, 37, 38, 39, 40, 41, 42, 43, 44, 45, 46, 47, 48, 49, 50, 51, 52, 53, 54, 55, 56, 57, 58, 59, 60, 61, 62, 63, 64, 65, 66, 67, 68

## CN_Jack3.5mm_3_Contacts_2_Switches
designator CN?
Stereo Jack with two break contacts
footprint CN_35mmJack_SJ1-3525N (3.5mm AUDIO JACK STEREO)
pins: 1, 2, 3, 4, 5

## CN_Jack3.5mm_4_Contacts_1_Switch
designator CN?, comment SJ-43515TS
3.5mm Audio Jack with four contacts and one switch; Manufacturer: CUI Inc; Note: CONN 3.5MM AUDIO JACK W/TIP SHNT
footprint CN_35mmJack_SJ1-3525N (3.5mm AUDIO JACK STEREO)
pins: 1, 3, 4, 5, 6

## CN_Jack_3.5mm_SMT
designator CN?, comment PJ-326
3.5mm Stereo Jack, SMT, Huayipeng Electronics Co.
footprint CN_3.5mm_Audio_Jack_SJ-3523-SMT (SJ-3523-SMT Audio Jack, 3.5mm, SMT, CUI Inc.)
pins: 3, 4, 5

## CN_Jack_Banana_4mm
designator CN?
4mm Banana Jack
footprint CN_SKT 4mm (pcb mounted insulated socket 4mm right angle)
pins: 1

## CN_JUMPER_2x3
designator JP?
2 contact jumper
footprint SIP-2 (0.1 inch Jumper)
pins: 1, 2, 3, 4, 5, 6

## CN_JUMPER_2x4
designator JP?
8 contact jumper
footprint SIP-2 (0.1 inch Jumper)
pins: 1, 2, 3, 4, 5, 6, 7, 8

## CN_MDJ-F-06
designator J?
Circular DIN, 6 Postion, Jack, Pitch 2.1/2.6 mm
footprint MDJ-F-06 (Connector; Circular DIN, Thru-Hole; 6 Position; Right Angle; Pitch 2.1/2.6 mm; Body 14 x 12.9 x 13 mm (WxTxH))
pcadlib MDJ-F-06 (Connector; Circular DIN, Thru-Hole; 6 Position; Right Angle; Pitch 2.1/2.6 mm; Body 14 x 12.9 x 13 mm (WxTxH))
signal-integrity model Circular DIN
footprint PS2-6PIN (PS2 Socket, 6 Pin, Through Hole)
pins: 1, 2, 3, 5, 6, 8, MH1 "Mounting Fixture", MH2 "Mounting Fixture", MH3 "Mounting Fixture"

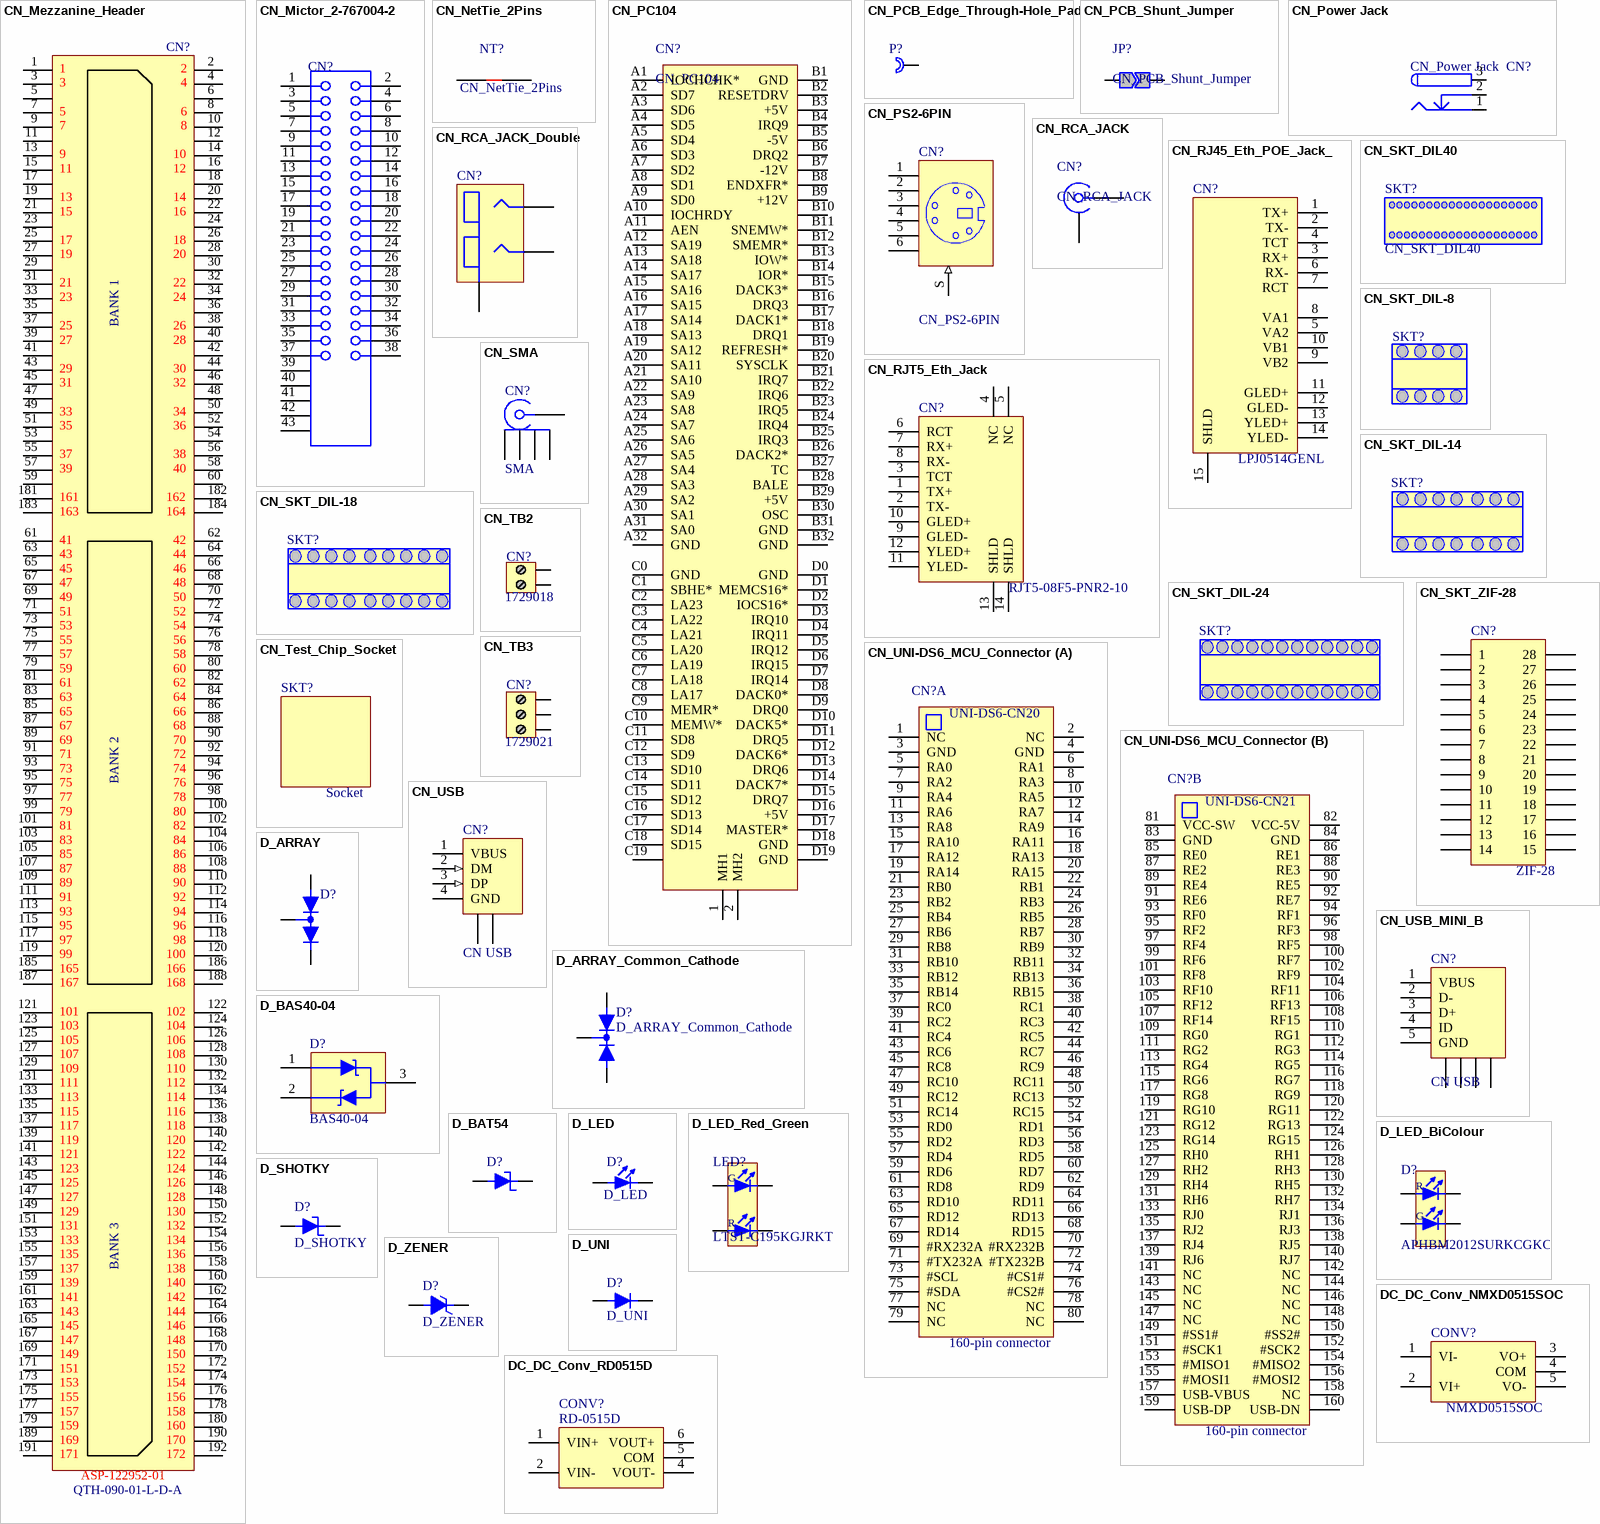
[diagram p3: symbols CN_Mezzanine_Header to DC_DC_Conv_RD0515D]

## CN_Mezzanine_Header
designator CN?, comment QTH-090-01-L-D-A
High-Speed Mezzanine Header, Samtec, QTH-090-01-L-D-A
footprint CN_QTH-090-01-X-D-A (0.50mm pitch, 180 pin, high speed terminal strip)
pins: 1, 2, 3, 4, 5, 6, 7, 8, 9, 10, 11, 12, 13, 14, 15, 16, 17, 18, 19, 20, 21, 22, 23, 24, 25, 26, 27, 28, 29, 30, 31, 32, 33, 34, 35, 36, 37, 38, 39, 40, 41, 42, 43, 44, 45, 46, 47, 48, 49, 50, 51, 52, 53, 54, 55, 56, 57, 58, 59, 60, 61, 62, 63, 64, 65, 66, 67, 68, 69, 70, 71, 72, 73, 74, 75, 76, 77, 78, 79, 80, 81, 82, 83, 84, 85, 86, 87, 88, 89, 90, 91, 92, 93, 94, 95, 96, 97, 98, 99, 100, 101, 102, 103, 104, 105, 106, 107, 108, 109, 110, 111, 112, 113, 114, 115, 116, 117, 118, 119, 120, 121, 122, 123, 124, 125, 126, 127, 128, 129, 130, 131, 132, 133, 134, 135, 136, 137, 138, 139, 140, 141, 142, 143, 144, 145, 146, 147, 148, 149, 150, 151, 152, 153, 154, 155, 156, 157, 158, 159, 160, 161, 162, 163, 164, 165, 166, 167, 168, 169, 170, 171, 172, 173, 174, 175, 176, 177, 178, 179, 180, 181 GND, 182 GND, 183 GND, 184 GND, 185 GND, 186 GND, 187 GND, 188 GND, 189 GND, 190 GND, 191 GND, 192 GND

## CN_Mictor_2-767004-2
designator CN?
Receptacle Assembly, Vertical, .025 [0.64] CL, Gull Wing Leads, MICTOR; PCB_Layout: Complies with manufacturer's recommendation.; DrillSize: Corresponds to nominal value.; PCB_Layout: Orientation hole size for standard applications, 0.094 Inches (+/-0.002). For slip-fit applications, 0.079 Inches (+/-0.001).; Note: Pins 39-43 are Ground Bus Leads.; Note: Mates with p/n 767006 to create right angle board-to-board configuration.
footprint CN_Mictor_2-767004-2 (Connector; High-Speed, Receptacle; 38 Position; Vertical)
signal-integrity model High-Speed
pins: 1, 2, 3, 4, 5, 6, 7, 8, 9, 10, 11, 12, 13, 14, 15, 16, 17, 18, 19, 20, 21, 22, 23, 24, 25, 26, 27, 28, 29, 30, 31, 32, 33, 34, 35, 36, 37, 38, 39 GND (power), 40 GND (power), 41 GND (power), 42 GND (power), 43 GND (power)

## CN_NetTie_2Pins
designator NT?  (net tie, no BOM)
Net Tie - 2 nets
pins: 1, 2

## CN_PC104
designator CN?
PC104; AMPMODU Interconnection System; Tyco Electronics
footprint CN_PC/104_Tyco (Tyco Electronics; PC/104 series; Part No. 1375793-2; Number of Positions = 104; 104 Loaded Positions; Contact Type = Stackthrough; 2.54 mm Centerline)
pins: 1 MH1, 2 MH2, A1 IOCHCHK*, A2 SD7, A3 SD6, A4 SD5, A5 SD4, A6 SD3, A7 SD2, A8 SD1, A9 SD0, A10 IOCHRDY, A11 AEN, A12 SA19, A13 SA18, A14 SA17, A15 SA16, A16 SA15, A17 SA14, A18 SA13, A19 SA12, A20 SA11, A21 SA10, A22 SA9, A23 SA8, A24 SA7, A25 SA6, A26 SA5, A27 SA4, A28 SA3, A29 SA2, A30 SA1, A31 SA0, A32 GND, B1 GND, B2 RESETDRV, B3 +5V, B4 IRQ9, B5 -5V, B6 DRQ2, B7 -12V, B8 ENDXFR*, B9 +12V, B10, B11 SNEMW*, B12 SMEMR*, B13 IOW*, B14 IOR*, B15 DACK3*, B16 DRQ3, B17 DACK1*, B18 DRQ1, B19 REFRESH*, B20 SYSCLK, B21 IRQ7, B22 IRQ6, B23 IRQ5, B24 IRQ4, B25 IRQ3, B26 DACK2*, B27 TC, B28 BALE, B29 +5V, B30 OSC, B31 GND, B32 GND, C0 GND, C1 SBHE*, C2 LA23, C3 LA22, C4 LA21, C5 LA20, C6 LA19, C7 LA18, C8 LA17, C9 MEMR*, C10 MEMW*, C11 SD8, C12 SD9, C13 SD10, C14 SD11, C15 SD12, C16 SD13, C17 SD14, C18 SD15, C19, D0 GND, D1 MEMCS16*, D2 IOCS16*, D3 IRQ10, D4 IRQ11, D5 IRQ12, D6 IRQ15, D7 IRQ14, D8 DACK0*, D9 DRQ0, D10 DACK5*, D11 DRQ5, D12 DACK6*, D13 DRQ6, D14 DACK7*, D15 DRQ7, D16 +5V, D17 MASTER*, D18 GND, D19 GND

## CN_PCB_Edge_Through-Hole_Pad
designator P?, comment Solder Pad  (value not drawn)
Test pin
footprint CN_Solder_Pad_PTH_Edge (Soldering pad for PCB on PCB designs)
pins: 1 P

## CN_PCB_Shunt_Jumper
designator JP?  (no BOM)
footprint PCBShuntJumper
pins: 1, 2

## CN_Power Jack
designator CN?
Low Voltage Power Supply Connector
signal-integrity model Connector
footprint CN_2.1mm_POWER_SOCKET (2.1mm Power Jack)
pins: 1 (power), 2 (power), 3 (power)

## CN_PS2-6PIN
designator CN?
6 Pin Through Hole PS2 Socket (Kycon P/N)
footprint PS2-6PIN (PS2 Socket, 6 Pin, Through Hole)
signal-integrity model Connector
pins: 1, 2, 3, 4, 5, 6, S (in)

## CN_RCA_JACK
designator CN?
RCA Jack; right angle
footprint TRC-005 (RCA Phono Jack, Right Angle, Thru-Hole, Body 20.8 x 9.8 x 11 mm (LxWxH))
pins: 1, 2

## CN_RCA_JACK_Double
designator CN?
Double RCA Jack
footprint CN_RCJ-22xx (RCA Jack; Dual; Right Angle; PCB Mount; Vertical)
pins: 1, 2, 3

## CN_RJ45_Eth_POE_Jack_
designator CN?, comment LPJ0514GENL
Ethernet Jack with POE and LEDs
footprint CN_Eth_LPJ0514GENL_Link-PP International Technology (RJ45 Ethernet Connector; PoE compatible; with magnetics and LEDs; Link-PP International Technology Co. Ltd.)
pins: 1 TX+, 2 TX-, 3 RX+, 4 TCT, 5 VA2, 6 RX-, 7 RCT, 8 VA1, 9 VB2, 10 VB1, 11 GLED+, 12 GLED-, 13 YLED+, 14 YLED-, 15 SHLD

## CN_RJT5_Eth_Jack
designator CN?, comment RJT5-08F5-PNR2-10
Ethernet Jack with magnetics and LEDs
footprint CN_RJT5-08F5-PNR2-10 (RJ45 Connector with magnetics and LEDs; eConn Electronics (Su-Zhou) Ltd.)
pins: 1 TX+, 2 TX-, 3 TCT, 4 NC hidden, 5 NC hidden, 6 RCT, 7 RX+, 8 RX-, 9 GLED-, 10 GLED+, 11 YLED-, 12 YLED+, 13 SHLD, 14 SHLD

## CN_SKT_DIL40
designator SKT?
DIP40 socket

## CN_SKT_DIL-8
designator SKT?  (mechanical)
DIP-8 Socket

## CN_SKT_DIL-14
designator SKT?  (mechanical)
DIP-14 Socket

## CN_SKT_DIL-18
designator SKT?  (mechanical)
DIL-18 Socket

## CN_SKT_DIL-24
designator SKT?  (mechanical)
DIL-18 Socket

## CN_SKT_ZIF-28
designator CN?, comment ZIF-28
Header, 14-Pin
footprint HDR1X14 (Connector; Header; 14 Position)
signal-integrity model Connector
pins: 1, 2, 3, 4, 5, 6, 7, 8, 9, 10, 11, 12, 13, 14, 15, 16, 17, 18, 19, 20, 21, 22, 23, 24, 25, 26, 27, 28

## CN_SMA
designator CN?, comment SMA
SMA connector
footprint CN_SMA (SMA Straight PCB Socket)
pins: 1, 3, 4, 5, 6

## CN_TB2
designator CN?, comment 1729018
2 pin Terminal Block Connector; Manufacturer: Phoenix Contact; Note: CONN TERM BLOCK 2POS 5MM PCB
footprint CN_Terminal Block - 5.0mm; 2 pin (2pin; Terminal Block Connector; 5.0mm pitch; Phoenix Contact; 1729018)
pins: 1, 2

## CN_TB3
designator CN?, comment 1729021
3 pin Terminal Block Connector; Manufacturer: Phoenix Contact; Note: CONN TERM BLOCK 3POS 5MM PCB
footprint CN_Terminal Block - 5.0mm; 3 pin (3pin; Terminal Block Connector; 5.0mm pitch; Phoenix Contact; 1729021)
pins: 1, 2, 3

## CN_Test_Chip_Socket
designator SKT?, comment Socket  (mechanical)
Socket for Test Chip

## CN_UNI-DS6_MCU_Connector
designator CN?, comment 160-pin connector
UNI-DS6 MCU connector; Mikroelektronika
footprint CN_UNI-DS6-MCU Connector (MCU Connector for UNI-DS6 Board from Mikroelektronika)
part A pins: 1 NC, 2 NC, 3 GND, 4 GND, 5 RA0, 6 RA1, 7 RA2, 8 RA3, 9 RA4, 10 RA5, 11 RA6, 12 RA7, 13 RA8, 14 RA9, 15 RA10, 16 RA11, 17 RA12, 18 RA13, 19 RA14, 20 RA15, 21 RB0, 22 RB1, 23 RB2, 24 RB3, 25 RB4, 26 RB5, 27 RB6, 28 RB7, 29 RB8, 30 RB9, 31 RB10, 32 RB11, 33 RB12, 34 RB13, 35 RB14, 36 RB15, 37 RC0, 38 RC1, 39 RC2, 40 RC3, 41 RC4, 42 RC5, 43 RC6, 44 RC7, 45 RC8, 46 RC9, 47 RC10, 48 RC11, 49 RC12, 50 RC13, 51 RC14, 52 RC15, 53 RD0, 54 RD1, 55 RD2, 56 RD3, 57 RD4, 58 RD5, 59 RD6, 60 RD7, 61 RD8, 62 RD9, 63 RD10, 64 RD11, 65 RD12, 66 RD13, 67 RD14, 68 RD15, 69 #RX232A, 70 #RX232B, 71 #TX232A, 72 #TX232B, 73 #SCL, 74 #CS1#, 75 #SDA, 76 #CS2#, 77 NC, 78 NC, 79 NC, 80 NC
part B pins: 81 VCC-SW, 82 VCC-5V, 83 GND, 84 GND, 85 RE0, 86 RE1, 87 RE2, 88 RE3, 89 RE4, 90 RE5, 91 RE6, 92 RE7, 93 RF0, 94 RF1, 95 RF2, 96 RF3, 97 RF4, 98 RF5, 99 RF6, 100 RF7, 101 RF8, 102 RF9, 103 RF10, 104 RF11, 105 RF12, 106 RF13, 107 RF14, 108 RF15, 109 RG0, 110 RG1, 111 RG2, 112 RG3, 113 RG4, 114 RG5, 115 RG6, 116 RG7, 117 RG8, 118 RG9, 119 RG10, 120 RG11, 121 RG12, 122 RG13, 123 RG14, 124 RG15, 125 RH0, 126 RH1, 127 RH2, 128 RH3, 129 RH4, 130 RH5, 131 RH6, 132 RH7, 133 RJ0, 134 RJ1, 135 RJ2, 136 RJ3, 137 RJ4, 138 RJ5, 139 RJ6, 140 RJ7, 141 NC, 142 NC, 143 NC, 144 NC, 145 NC, 146 NC, 147 NC, 148 NC, 149 #SS1#, 150 #SS2#, 151 #SCK1, 152 #SCK2, 153 #MISO1, 154 #MISO2, 155 #MOSI1, 156 #MOSI2, 157 USB-VBUS, 158 NC, 159 USB-DP, 160 USB-DN

## CN_USB
designator CN?, comment CN USB
USB connector
footprint USB-SKT B (Connector; USB1.1, Type B, Thru-Hole; 4 Position; Right Angle)
footprint USB-SKT A (Connector; USB2.0, Type A, Thru-Hole; 4 Position; Right Angle)
pins: 1 VBUS, 2 DM (in), 3 DP (in), 4 GND, 5 SHLD, 6 SHLD

## CN_USB_MINI_B
designator CN?, comment CN USB
Mini USB connector; SMD
footprint CN_USB_MINI_B
pins: 1 VBUS, 2 D-, 3 D+, 4 ID, 5 GND, 6 SHLD, 7 SHLD, 8 SHLD, 9 SHLD

## D_ARRAY
designator D?
Dual diode array - SOT-23
footprint SOT23-3AL (SOT23 SMT Package)
pins: 1, 2, 3

## D_ARRAY_Common_Cathode
designator D?
Dual diode array; Common Cathode - SOT-23
footprint SOT23-3AL (SOT23 SMT Package)
pins: 1, 2, 3

## D_BAS40-04
designator D?, comment BAS40-04
Shottky Diode Pair; Manufacturer: Micro Commercial Components; ManufacturerPartNo: BAS40-04-TP
footprint SOT23-3AL (SOT23 SMT Package)
pins: 1, 2, 3

## D_BAT54
designator D?
Schottky Diode - SOT-23
simulation model SKYDIODE (Diode)
signal-integrity model D Schottky
footprint SOT23-3AL (SOT23 SMT Package)
pins: 1 A, 3 C

## D_LED
designator D?
Typical LED diode
simulation model LED0 (Diode)
footprint LEDC2012-0805 (Chip LED diode; Body 2 x 1.3 mm (LxW typ))
footprint LEDC3216-1206 (Chip LED diode; Body 3.2 x 1.6 mm (LxW typ))
footprint LED_L-1034 (2mm; Flat Top LED Lamp)
pins: 1 K, 2 A

## D_LED_BiColour
designator D?, comment APHBM2012SURKCGKC
LED diode, Bi Colour; Kingbright; APHBM2012SURKCGKC
simulation model LED0 (Diode)
footprint LEDC2012-0805_Bicolour (Chip LED, 4-Leads, Body 2.0x1.5mm, IPC Medium Density)
pins: 1 A_R, 2 K_R, 3 K_G, 4 A_G

## D_LED_Red_Green
designator LED?, comment LTST-C195KGJRKT
LED diode, Bi Colour; Kingbright; APHBM2012SURKCGKC; Manufacturer: Lite-On Inc; Note: LED GREEN/RED BICOLOR 0606 SMD
simulation model LED0 (Diode)
footprint LEDC2012-0805_Bicolour (Chip LED, 4-Leads, Body 2.0x1.5mm, IPC Medium Density)
pins: 1 A_G, 2 A_R, 3 K_G, 4 K_R

## D_SHOTKY
designator D?
Schottky Diode
simulation model SKYDIODE (Diode)
signal-integrity model D Schottky
footprint SOD-323 (SOD-323/SC-76; 2 Leads; Body 1.7 x 1.3 mm, (LxW))
footprint MELF-D3516-1406 (Metal Electrode Face (MELF) Diode; Body 3.5 x 1.7 mm (LxDia))
footprint MELF-D5023-2009 (Metal Electrode Face (MELF) Diode; Body 5 x 2.5 mm (LxDia))
footprint SMA (DO-214-AC/SMA; 2 C-Bend Leads; Body 5 x 2.7 mm, inc. leads (LxW))
footprint SMB (DO-214-AA/SMB; 2 C-Bend Leads; Body 5.3 x 3.6 mm, inc. leads (LxW))
footprint SMC (DO-214-AB/SMC; 2 C-Bend Leads; Body 7.9 x 5.9 mm, inc. leads (LxW))
footprint SOD-123 (SOD-123; 2 Leads; Body 2.8 x 1.7 mm, (LxW))
footprint SOD-323 (SOD-323/SC-76; 2 Leads; Body 1.8 x 1.4 mm, (LxW))
footprint SOD-523 (SOD-523; 2 Leads; Body 1.3 x 0.35 mm, (LxW))
pins: 1 K, 2 A

## D_UNI
designator D?
Low-Loss RF Switching Diode; Note: Pin 2 is not connected and not drawn.
simulation model BAT18 (DIODE)
footprint MELF-D3516-1406 (Metal Electrode Face (MELF) Diode; Body 3.5 x 1.7 mm (LxDia))
footprint MELF-D5023-2009 (Metal Electrode Face (MELF) Diode; Body 5 x 2.5 mm (LxDia))
footprint SMA (DO-214-AC/SMA; 2 C-Bend Leads; Body 5 x 2.7 mm, inc. leads (LxW))
footprint SMB (DO-214-AA/SMB; 2 C-Bend Leads; Body 5.3 x 3.6 mm, inc. leads (LxW))
footprint SMC (DO-214-AB/SMC; 2 C-Bend Leads; Body 7.9 x 5.9 mm, inc. leads (LxW))
pins: 1 K, 2 A

## D_ZENER
designator D?
Zener Diode
footprint DIODE-0.7 (Zener Diode; 2 Leads)
simulation model ZENER (Diode)
signal-integrity model D Zener
pins: 1 K, 2 A

## DC_DC_Conv_NMXD0515SOC
designator CONV?, comment NMXD0515SOC
Isolated 5W Regulated Dual Output DC/DC Converter
pins: 1 VI-, 2 VI+, 3 VO+, 4 COM, 5 VO-

## DC_DC_Conv_RD0515D
designator CONV?, comment RD-0515D
pins: 1 VIN+, 2 VIN-, 4 VOUT-, 5 COM, 6 VOUT+

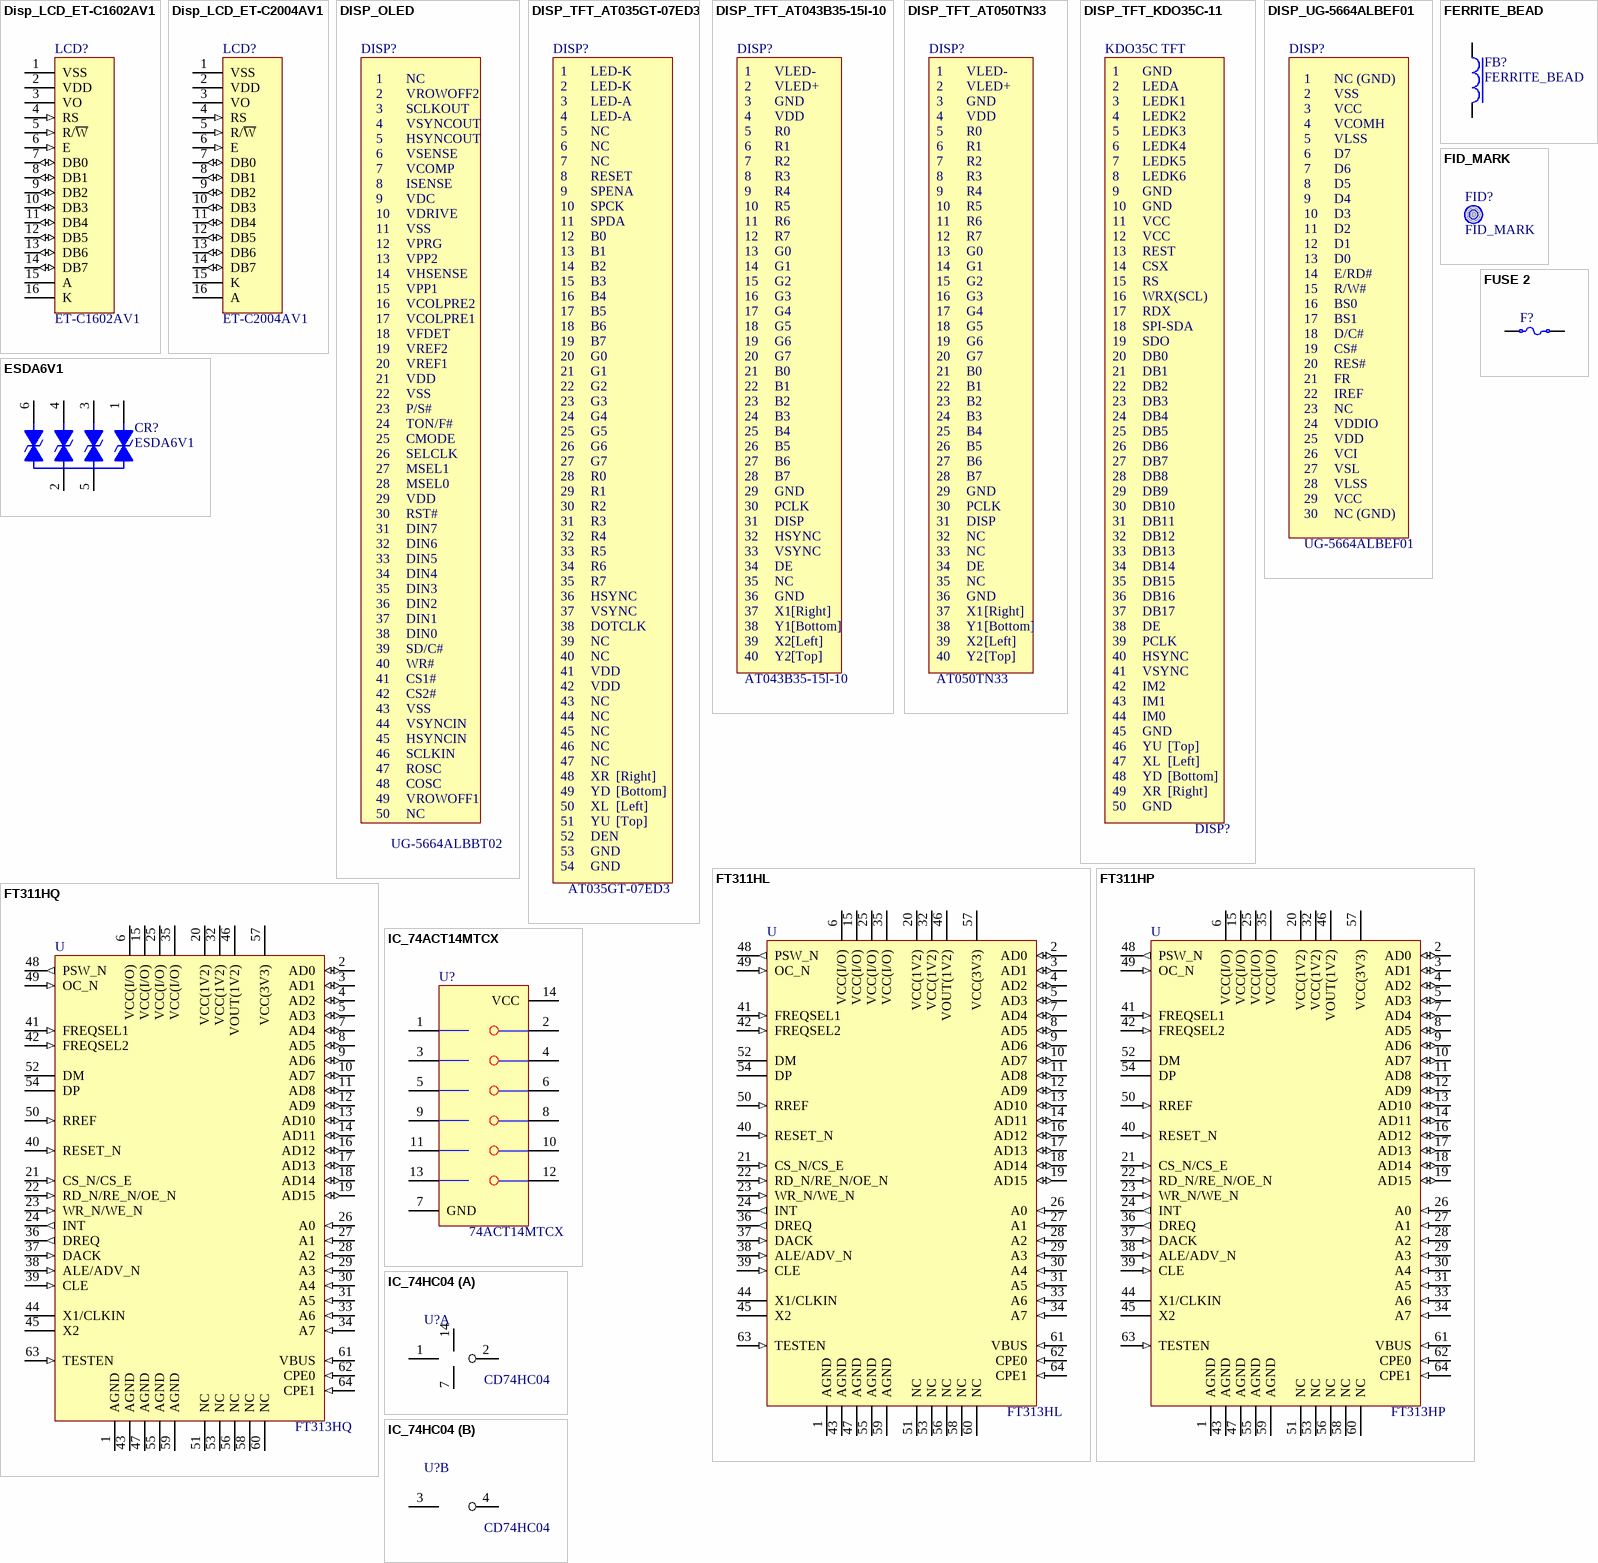
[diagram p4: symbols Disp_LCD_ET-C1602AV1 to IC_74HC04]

## Disp_LCD_ET-C1602AV1
designator LCD?, comment ET-C1602AV1
LCD Display; 16X2
footprint DISP_LCD_ET-C2004AV1 (LCD Module; 20x4)
pins: 1 VSS (power), 2 VDD (power), 3 VO, 4 RS (in), 5 R/~{W} (in), 6 E (in), 7 DB0 (io), 8 DB1 (io), 9 DB2 (io), 10 DB3 (io), 11 DB4 (io), 12 DB5 (io), 13 DB6 (io), 14 DB7 (io), 15 A (power), 16 K (power)

## Disp_LCD_ET-C2004AV1
designator LCD?, comment ET-C2004AV1
LCD Display; 20x4
footprint DISP_LCD_ET-C2004AV1 (LCD Module; 20x4)
pins: 1 VSS (power), 2 VDD (power), 3 VO, 4 RS (in), 5 R/~{W} (in), 6 E (in), 7 DB0 (io), 8 DB1 (io), 9 DB2 (io), 10 DB3 (io), 11 DB4 (io), 12 DB5 (io), 13 DB6 (io), 14 DB7 (io), 15 K (power), 16 A (power)

## DISP_OLED
designator DISP?, comment UG-5664ALBBT02  (mechanical)
256X64 pixels OLED display with STV8105 OLED Passive Matrix Controller/Driver
footprint OLEDDisplay (UG-5664ALBBT02; Folding Type; OEL Display Module; 256x64 pixels; Monochrome; TCP Package)

## DISP_TFT_AT035GT-07ED3
designator DISP?, comment AT035GT-07ED3  (mechanical)
320x240 pixels TFT display with Touch screen

## DISP_TFT_AT043B35-15l-10
designator DISP?, comment AT043B35-15l-10  (mechanical)
4.3"; 480x272 pixels; TFT display with Touch screen A-Tops Electronics Company

## DISP_TFT_AT050TN33
designator DISP?, comment AT050TN33  (mechanical)
5"; 480x272 pixels; TFT display with Touch screen A-Tops Electronics Company

## DISP_TFT_KDO35C-11
designator DISP?, comment KDO35C TFT

## DISP_UG-5664ALBEF01
designator DISP?, comment UG-5664ALBEF01  (mechanical)
256X64 pixels OLED display with SSD1322U OLED Passive Matrix Controller/Driver
footprint DISP_OLED_UG-5664ALBEF01 (UG-5664ALBEF01; Folding Type; OEL Display Module; 256x64 pixels; Monochrome; TCP Package)

## ESDA6V1
designator CR?
QUAD BIDIRECTIONAL TRANSIL  SUPPRESSOR FOR ESD PROTECTION
footprint SOT23-6N (SOT23, 6-Leads, Body 3.0x3.0mm (max), Pitch 0.95mm, IPC Medium Density)
pins: 1, 2, 3, 4, 5, 6

## FERRITE_BEAD
designator FB?
Chip Ferrite Bead 0805
footprint IND-C2012-0805 (Chip Inductor; Body 2 x 1.2 mm (LxW typ))
pins: 1, 2

## FID_MARK
designator FID?
Fiducial mark for pitch less than 0.65mm
footprint FIDUCIAL MARK

## FT311HL
designator U, comment FT313HL
FT313HL High Speed USB Host
footprint LQFP50P10X10-64N (LQFP, 64-Leads, Body 10x10mm (max), Pitch 0.50mm, IPC Medium Density)
pins: 1 AGND, 2 AD0 (io), 3 AD1 (io), 4 AD2 (io), 5 AD3 (io), 6 VCC(I/O) (power), 7 AD4 (io), 8 AD5 (io), 9 AD6 (io), 10 AD7 (io), 11 AD8 (io), 12 AD9 (io), 13 AD10 (io), 14 AD11 (io), 15 VCC(I/O) (power), 16 AD12 (io), 17 AD13 (io), 18 AD14 (io), 19 AD15 (io), 20 VCC(1V2) (power), 21 CS_N/CS_E (in), 22 RD_N/RE_N/OE_N (in), 23 WR_N/WE_N (in), 24 INT (out), 25 VCC(I/O) (power), 26 A0 (in), 27 A1 (in), 28 A2 (in), 29 A3 (in), 30 A4 (in), 31 A5 (in), 32 VCC(1V2) (power), 33 A6 (in), 34 A7 (in), 35 VCC(I/O) (power), 36 DREQ (out), 37 DACK (in), 38 ALE/ADV_N (in), 39 CLE (in), 40 RESET_N (in), 41 FREQSEL1 (in), 42 FREQSEL2 (in), 43 AGND, 44 X1/CLKIN, 45 X2, 46 VOUT(1V2) (power), 47 AGND, 48 PSW_N (out), 49 OC_N (in), 50 RREF (in), 51 NC, 52 DM, 53 NC, 54 DP, 55 AGND, 56 NC, 57 VCC(3V3) (power), 58 NC, 59 AGND, 60 NC, 61 VBUS (in), 62 CPE0 (in), 63 TESTEN (in), 64 CPE1 (in)

## FT311HP
designator U, comment FT313HP
FT313HP High Speed USB Host
pins: 1 AGND, 2 AD0 (io), 3 AD1 (io), 4 AD2 (io), 5 AD3 (io), 6 VCC(I/O) (power), 7 AD4 (io), 8 AD5 (io), 9 AD6 (io), 10 AD7 (io), 11 AD8 (io), 12 AD9 (io), 13 AD10 (io), 14 AD11 (io), 15 VCC(I/O) (power), 16 AD12 (io), 17 AD13 (io), 18 AD14 (io), 19 AD15 (io), 20 VCC(1V2) (power), 21 CS_N/CS_E (in), 22 RD_N/RE_N/OE_N (in), 23 WR_N/WE_N (in), 24 INT (out), 25 VCC(I/O) (power), 26 A0 (in), 27 A1 (in), 28 A2 (in), 29 A3 (in), 30 A4 (in), 31 A5 (in), 32 VCC(1V2) (power), 33 A6 (in), 34 A7 (in), 35 VCC(I/O) (power), 36 DREQ (out), 37 DACK (in), 38 ALE/ADV_N (in), 39 CLE (in), 40 RESET_N (in), 41 FREQSEL1 (in), 42 FREQSEL2 (in), 43 AGND, 44 X1/CLKIN, 45 X2, 46 VOUT(1V2) (power), 47 AGND, 48 PSW_N (out), 49 OC_N (in), 50 RREF (in), 51 NC, 52 DM, 53 NC, 54 DP, 55 AGND, 56 NC, 57 VCC(3V3) (power), 58 NC, 59 AGND, 60 NC, 61 VBUS (in), 62 CPE0 (in), 63 TESTEN (in), 64 CPE1 (in)

## FT311HQ
designator U, comment FT313HQ
FT313HQ High Speed USB Host
pins: 1 AGND, 2 AD0 (io), 3 AD1 (io), 4 AD2 (io), 5 AD3 (io), 6 VCC(I/O) (power), 7 AD4 (io), 8 AD5 (io), 9 AD6 (io), 10 AD7 (io), 11 AD8 (io), 12 AD9 (io), 13 AD10 (io), 14 AD11 (io), 15 VCC(I/O) (power), 16 AD12 (io), 17 AD13 (io), 18 AD14 (io), 19 AD15 (io), 20 VCC(1V2) (power), 21 CS_N/CS_E (in), 22 RD_N/RE_N/OE_N (in), 23 WR_N/WE_N (in), 24 INT (out), 25 VCC(I/O) (power), 26 A0 (in), 27 A1 (in), 28 A2 (in), 29 A3 (in), 30 A4 (in), 31 A5 (in), 32 VCC(1V2) (power), 33 A6 (in), 34 A7 (in), 35 VCC(I/O) (power), 36 DREQ (out), 37 DACK (in), 38 ALE/ADV_N (in), 39 CLE (in), 40 RESET_N (in), 41 FREQSEL1 (in), 42 FREQSEL2 (in), 43 AGND, 44 X1/CLKIN, 45 X2, 46 VOUT(1V2) (power), 47 AGND, 48 PSW_N (out), 49 OC_N (in), 50 RREF (in), 51 NC, 52 DM, 53 NC, 54 DP, 55 AGND, 56 NC, 57 VCC(3V3) (power), 58 NC, 59 AGND, 60 NC, 61 VBUS (in), 62 CPE0 (in), 63 TESTEN (in), 64 CPE1 (in)

## FUSE 2
designator F?
Fuse
simulation model FUSE (Spice Subcircuit)
footprint CR2012-0805 (Chip Resistor; Body 2 x 1.3 mm (LxW typ))
footprint CR3216-1206 (Chip Resistor; Body 3.2 x 1.6 mm (LxW typ))
footprint CR3216-1206 (Chip Resistor; Body 3.2 x 1.6 mm (LxW typ))
footprint Fuse_SMD (Fuse SMT; Picofuse series; Littelfuse)
pins: 1, 2

## IC_74ACT14MTCX
designator U?, comment 74ACT14MTCX
Quad Schmitt Inverter
footprint TSOP65P640X110-14N (TSOP, 14-Leads, Body 5.1x4.5mm (max), Pitch 0.65mm, IPC Medium Density)
pins: 1 1A, 2 1Y, 3 2A, 4 2Y, 5 3A, 6 3Y, 7 GND, 8 4Y, 9 4A, 10 5Y, 11 5A, 12 6Y, 13 6A, 14 VCC

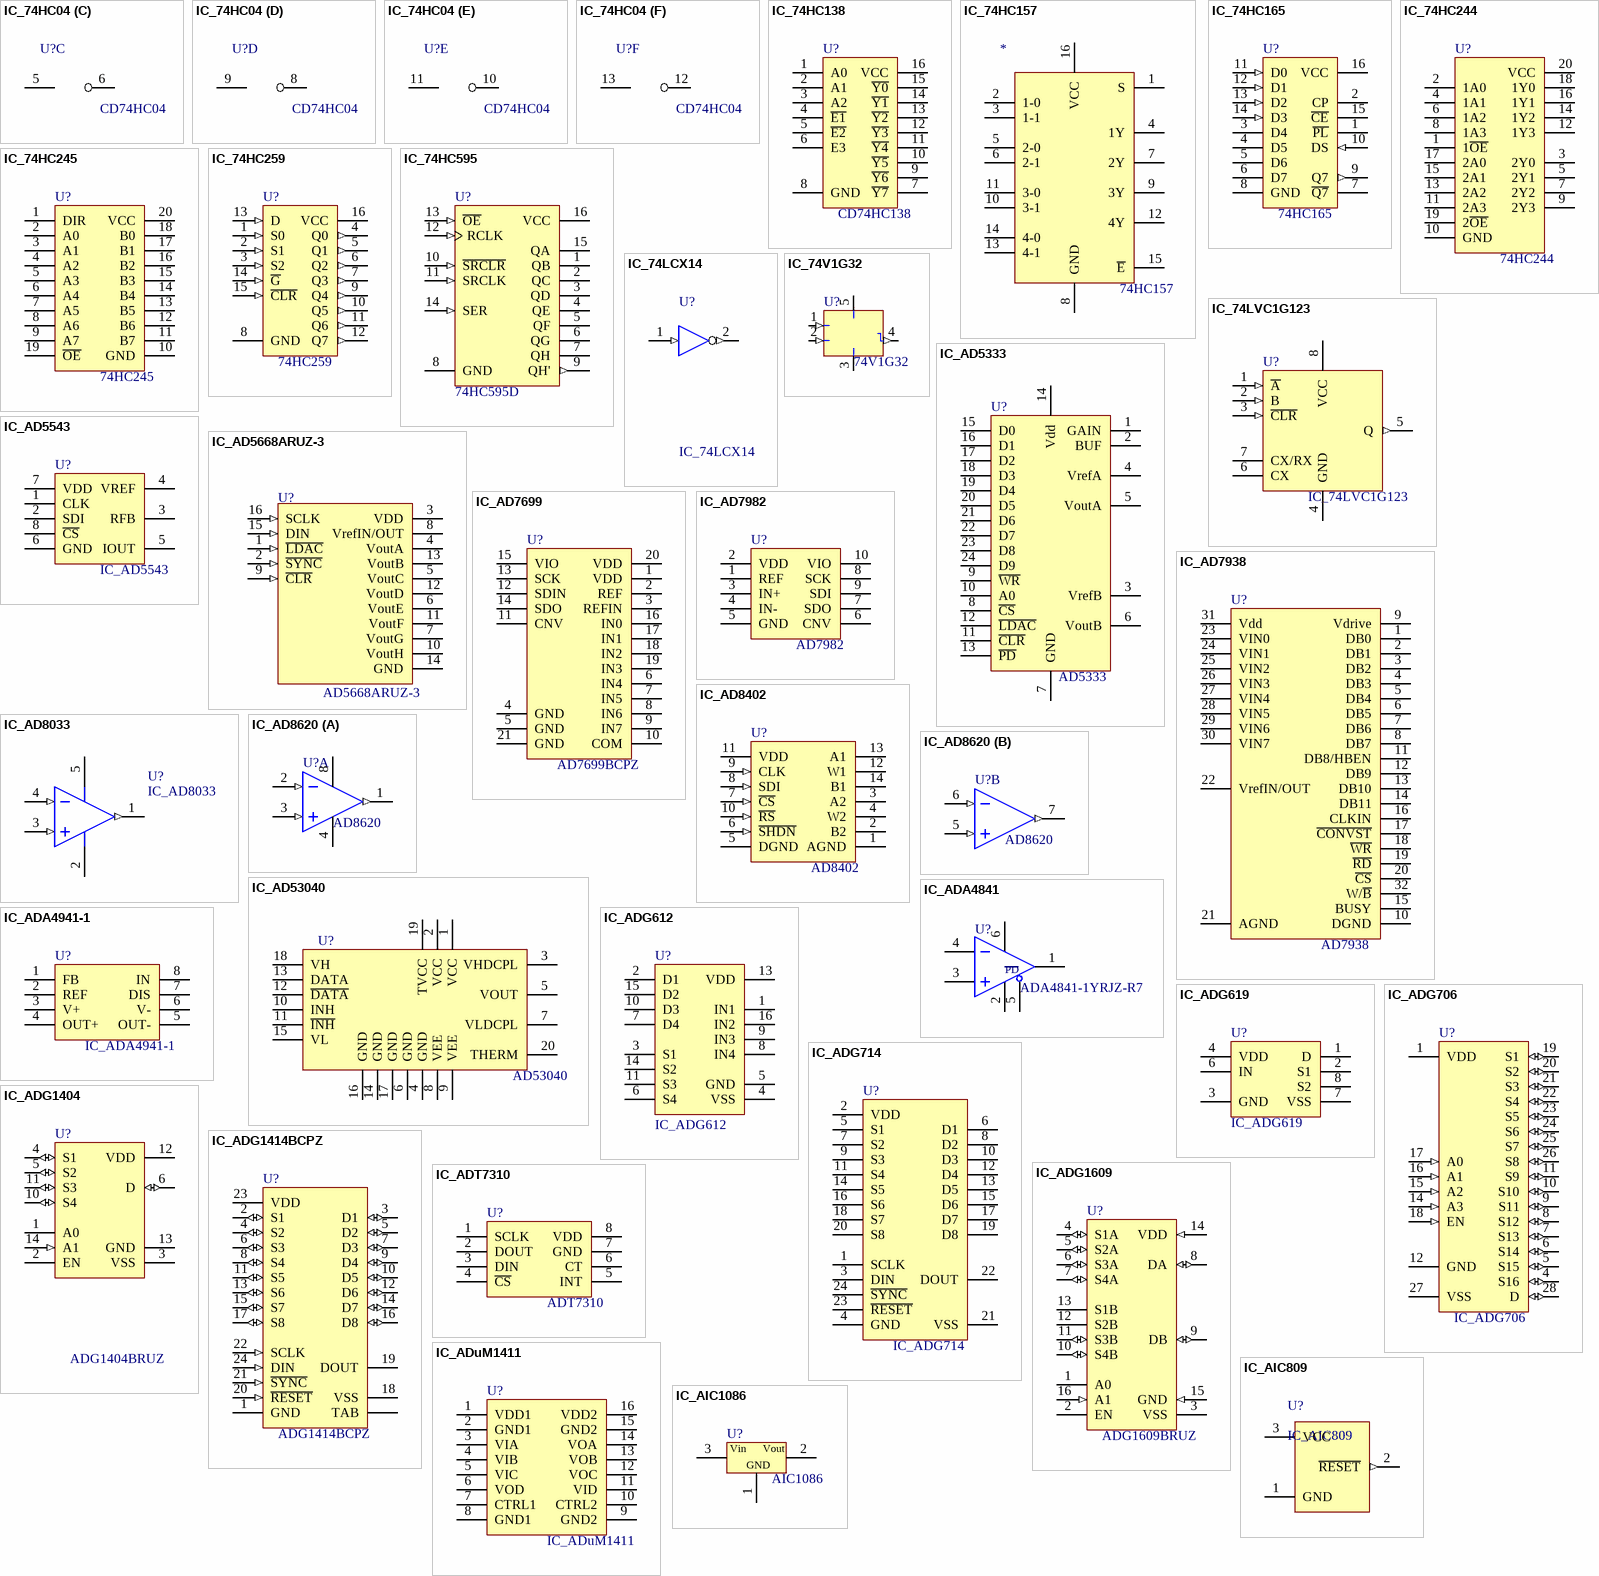
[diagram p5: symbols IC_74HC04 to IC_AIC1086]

## IC_74HC04
designator U?, comment CD74HC04
High-Speed CMOS Logic Hex Inverter
footprint SO-14N (14-Pin Small Outline Integrated Circuit 1.27 mm Pitch, IPC Medium Density)
part A pins: 1 1A, 2 ~{1Y}, 7 GND, 14 VCC
part B pins: 3 2A, 4 ~{2Y}
part C pins: 5 3A, 6 ~{3Y}
part D pins: 8 ~{4Y}, 9 4A
part E pins: 10 ~{5Y}, 11 5A
part F pins: 12 ~{6Y}, 13 6A

## IC_74HC138
designator U?, comment CD74HC138
High-Speed CMOS Logic 3- to 8-Line Decoder/ Demultiplexer, Inverting
footprint SO-16N (16-Pin Small Outline Integrated Circuit 1.27 mm Pitch, IPC Medium Density)
pins: 1 A0, 2 A1, 3 A2, 4 ~{E1}, 5 ~{E2}, 6 E3, 7 ~{Y7}, 8 GND, 9 ~{Y6}, 10 ~{Y5}, 11 ~{Y4}, 12 ~{Y3}, 13 ~{Y2}, 14 ~{Y1}, 15 ~{Y0}, 16 VCC

## IC_74HC157
designator *, comment 74HC157
pins: 1 S, 2 1-0, 3 1-1, 4 1Y, 5 2-0, 6 2-1, 7 2Y, 8 GND, 9 3Y, 10 3-1, 11 3-0, 12 4Y, 13 4-1, 14 4-0, 15 ~{E}, 16 VCC

## IC_74HC165
designator U?, comment 74HC165
8-Bit; Parallel Input Shift Register
3D model D016 (16-Pin Small Outline Integrated Circuit 1.27 mm Pitch)
signal-integrity model SN74HC595D
footprint SO-16_N (16-Pin Small Outline Integrated Circuit 1.27 mm Pitch, IPC Medium Density)
footprint TSSOP65P640X120-16N (TSOP, 16-Leads, Body 5.1x4.5mm (max), Pitch 0.65mm, IPC Medium Density)
pins: 1 ~{PL} (hiz), 2 CP (hiz), 3 D4 (hiz), 4 D5 (hiz), 5 D6 (hiz), 6 D7 (hiz), 7 ~{Q7} (hiz), 8 GND (power), 9 Q7 (out), 10 DS (in), 11 D0 (in), 12 D1 (in), 13 D2 (in), 14 D3 (in), 15 ~{CE} (hiz), 16 VCC (power)

## IC_74HC244
designator U?, comment 74HC244
Octal buffer/line driver; 3-state
footprint SO-20N (SOIC, 20-Leads, Body 13.0x7.8mm (max), Pitch 1.27mm, IPC Medium Density)
pins: 1 1~{OE}, 2 1A0, 3 2Y0, 4 1A1, 5 2Y1, 6 1A2, 7 2Y2, 8 1A3, 9 2Y3, 10 GND, 11 2A3, 12 1Y3, 13 2A2, 14 1Y2, 15 2A1, 16 1Y1, 17 2A0, 18 1Y0, 19 2~{OE}, 20 VCC

## IC_74HC245
designator U?, comment 74HC245
Octal bus tranceiver; 3-state
footprint SO-20N (SOIC, 20-Leads, Body 13.0x7.8mm (max), Pitch 1.27mm, IPC Medium Density)
pins: 1 DIR, 2 A0, 3 A1, 4 A2, 5 A3, 6 A4, 7 A5, 8 A6, 9 A7, 10 GND, 11 B7, 12 B6, 13 B5, 14 B4, 15 B3, 16 B2, 17 B1, 18 B0, 19 ~{OE}, 20 VCC

## IC_74HC259
designator U?, comment 74HC259
High-Speed CMOS Logic 8-bit addressable latch
footprint SO-16N (16-Pin Small Outline Integrated Circuit 1.27 mm Pitch, IPC Medium Density)
pins: 1 S0 (in), 2 S1 (in), 3 S2 (in), 4 Q0 (out), 5 Q1 (out), 6 Q2 (out), 7 Q3 (out), 8 GND (power), 9 Q4 (out), 10 Q5 (out), 11 Q6 (out), 12 Q7 (out), 13 D (in), 14 ~{G} (in), 15 ~{CLR} (in), 16 VCC (power)

## IC_74HC595
designator U?, comment 74HC595D
8-Bit Shift Register with 3-State Output Registers
3D model D016 (16-Pin Small Outline Integrated Circuit 1.27 mm Pitch)
signal-integrity model SN74HC595D
footprint SO-16_N (16-Pin Small Outline Integrated Circuit 1.27 mm Pitch, IPC Medium Density)
footprint TSSOP127P600-16N
pins: 1 QB (hiz), 2 QC (hiz), 3 QD (hiz), 4 QE (hiz), 5 QF (hiz), 6 QG (hiz), 7 QH (hiz), 8 GND (power), 9 QH' (out), 10 ~{SRCLR} (in), 11 SRCLK (in), 12 RCLK (in), 13 ~{OE} (in), 14 SER (in), 15 QA (hiz), 16 VCC (power)

## IC_74LCX14
designator U?
Low Voltage Hex Inverter  with 5V Tolerant Schmitt Trigger Inputs; Manufacturer: Fairchild
footprint SO-14_N (14-Pin Small Outline Integrated Circuit 1.27 mm Pitch, IPC Medium Density)
signal-integrity model SN7414N
footprint TSSOP-14
pins: 1 A (in), 2 Y (out), 7 GND (power) hidden to GND, 14 VCC (power) hidden to VCC

## IC_74LVC1G123
designator U?
Retriggerable Monostable Multivibrator
footprint SOP65P400X130-8N (SOP, 8-Leads, Body 3.2x2.9mm (max), Pitch 0.65mm, IPC Medium Density)
footprint SSOP50P310X90-8N (SSOP, 8-Leads, Body 2.1x2.4mm (max), Pitch 0.50mm, IPC Medium Density)
pins: 1 ~{A} (in), 2 B (in), 3 ~{CLR} (in), 4 GND (power), 5 Q (out), 6 CX, 7 CX/RX, 8 VCC (power)

## IC_74V1G32
designator U?, comment 74V1G32
Single 2-Input OR Gate;; Manufacturer: STMicroelectronics; ManufacturerPartNo: 74V1G32STR
footprint SOT23-5AL (SOT23, 5-Leads, Body 2.9x1.6mm, Pitch 0.95mm, Lead Span 2.8mm, IPC High Density)
pins: 1 A (in), 2 B (in), 3 GND (power), 4 Y (out), 5 VCC (power)

## IC_AD5333
designator U?, comment AD5333
2.5 V to 5.5 V, 230u A, Parallel Interface  Dual Voltage-Output 10-Bit DAC
footprint TSSOP65P640X110-24N (TSSOP, 24-Leads, Body 7.9x4.5mm (max), Pitch 0.65mm, IPC Medium Density)
pins: 1 GAIN, 2 BUF, 3 VrefB, 4 VrefA, 5 VoutA, 6 VoutB, 7 GND, 8 ~{CS}, 9 ~{WR}, 10 A0, 11 ~{CLR}, 12 ~{LDAC}, 13 ~{PD}, 14 Vdd, 15 D0, 16 D1, 17 D2, 18 D3, 19 D4, 20 D5, 21 D6, 22 D7, 23 D8, 24 D9

## IC_AD5543
designator U?
Current Output/Serial Input,  16-Bit DAC
footprint MSOP65P490X110-8N (MSOP, 8-Leads, Body 3.1x3.1mm (max), Pitch 0.65mm, IPC Medium Density)
pins: 1 CLK, 2 SDI, 3 RFB, 4 VREF, 5 IOUT, 6 GND, 7 VDD, 8 ~{CS}

## IC_AD5668ARUZ-3
designator U?, comment AD5668ARUZ-3
Octal, 16-Bit DAC with 5 ppm/°C  On-Chip Reference in 16-Lead TSSOP; Analog Devices; Manufacturer: Analog Devices Inc; Note: IC DAC 16BIT LP OCT 5V 16-TSSOP
pins: 1 ~{LDAC} (in), 2 ~{SYNC} (in), 3 VDD (power), 4 VoutA, 5 VoutC, 6 VoutE, 7 VoutG, 8 VrefIN/OUT, 9 ~{CLR} (in), 10 VoutH, 11 VoutF, 12 VoutD, 13 VoutB, 14 GND (power), 15 DIN (in), 16 SCLK (in)

## IC_AD7699
designator U?, comment AD7699BCPZ
16-Bit, 8-Channel,  500 kSPS PulSAR ADC; Analog Devices
pins: 1 VDD, 2 REF, 3 REFIN, 4 GND, 5 GND, 6 IN4, 7 IN5, 8 IN6, 9 IN7, 10 COM, 11 CNV, 12 SDIN, 13 SCK, 14 SDO, 15 VIO, 16 IN0, 17 IN1, 18 IN2, 19 IN3, 20 VDD, 21 GND

## IC_AD7938
designator U?, comment AD7938
8-Channel, 1.5 MSPS, 12-Bit Parallel ADCs with a Sequencer
footprint TQFP80P900X900X160-32N (TQFP, 32-Leads, Body 9.2x9.2mm (max), Pitch 0.80mm, IPC Medium Density)
pins: 1 DB0, 2 DB1, 3 DB2, 4 DB3, 5 DB4, 6 DB5, 7 DB6, 8 DB7, 9 Vdrive, 10 DGND, 11 DB8/HBEN, 12 DB9, 13 DB10, 14 DB11, 15 BUSY, 16 CLKIN, 17 ~{CONVST}, 18 ~{WR}, 19 ~{RD}, 20 ~{CS}, 21 AGND, 22 VrefIN/OUT, 23 VIN0, 24 VIN1, 25 VIN2, 26 VIN3, 27 VIN4, 28 VIN5, 29 VIN6, 30 VIN7, 31 Vdd, 32 W/~{B}

## IC_AD7982
designator U?, comment AD7982
18-Bit, 1 MSPS PulSAR 7.0 mW  ADC in MSOP/QFN
pins: 1 REF, 2 VDD, 3 IN+, 4 IN-, 5 GND, 6 CNV, 7 SDO, 8 SCK, 9 SDI, 10 VIO

## IC_AD8033
designator U?
Low Cost, 80 MHz  FastFET (tm) Op Amps; Manufacturer: Analog Devices; ManufacturerPartNo: AD8033AR
footprint SC70-65P210x110-5N (SC70, 5-Leads, Body 2.2x2.4mm (max), Pitch 0.65mm, IPC Medium Density)
pins: 1 OUT (out), 2 VS-, 3 IN+ (in), 4 IN- (in), 5 VS+

## IC_AD8402
designator U?, comment AD8402
Dual, 256-Position, SPI  Digital Potentiometer
footprint TSOP65P640X110-14N (TSOP, 14-Leads, Body 5.1x4.5mm (max), Pitch 0.65mm, IPC Medium Density)
pins: 1 AGND (power), 2 B2, 3 A2, 4 W2, 5 DGND (power), 6 ~{SHDN} (in), 7 ~{CS} (in), 8 SDI (in), 9 CLK (in), 10 ~{RS} (in), 11 VDD (power), 12 W1, 13 A1, 14 B1

## IC_AD8620
designator U?, comment AD8620
Low power dual operational amplifier; Manufacturer: Analog Devices; ManufacturerPartNo: AD8033AR
footprint SO-8N (8-Pin Small Outline Integrated Circuit 1.27 mm Pitch, IPC Medium Density)
part A pins: 1 OUT1 (out), 2 IN-1 (in), 3 IN+1 (in), 4 VSS, 8 VCC
part B pins: 5 IN+2 (in), 6 IN-2 (in), 7 OUT2 (out)

## IC_AD53040
designator U?, comment AD53040
Ultrahigh Speed Pin Driver  with Inhibit Mode
pins: 1 VCC, 2 VCC, 3 VHDCPL, 4 GND, 5 VOUT, 6 GND, 7 VLDCPL, 8 VEE, 9 VEE, 10 INH, 11 ~{INH}, 12 ~{DATA}, 13 DATA, 14 GND, 15 VL, 16 GND, 17 GND, 18 VH, 19 TVCC, 20 THERM

## IC_ADA4841
designator U?, comment ADA4841-1YRJZ-R7
Low Power, Low Noise and Distortion,  Rail-to-Rail Output Amplifier in SOT23-6; Analog Devices
pins: 1 VOUT, 2 -VS, 3 +IN, 4 -IN, 5 ~{PD}, 6 +VS

## IC_ADA4941-1
designator U?
Single-Supply, Differential  18-Bit ADC Driver
pins: 1 FB, 2 REF, 3 V+, 4 OUT+, 5 OUT-, 6 V-, 7 DIS, 8 IN

## IC_ADG612
designator U?
1 pC Charge Injection, 100 pA Leakage,  CMOS  +/-5 V;+5 V;+3 V Quad SPST Switches; Manufacturer: Analog Devices; ManufacturerPartNo: ADG612YRUZ
footprint TSSOP127P600-16N
pins: 1 IN1, 2 D1, 3 S1, 4 VSS, 5 GND, 6 S4, 7 D4, 8 IN4, 9 IN3, 10 D3, 11 S3, 12 NC hidden, 13 VDD, 14 S2, 15 D2, 16 IN2

## IC_ADG619
designator U?
CMOS, ±5 V/+5 V,  4 Ohm, Single SPDT Switches; Manufacturer: Analog Devices; ManufacturerPartNo: ADG619BRMZ
footprint SOT23-8AL (SOT23 8-PIN 0.65mm PITCH)
pins: 1 D, 2 S1, 3 GND, 4 VDD, 5 NC hidden, 6 IN, 7 VSS, 8 S2

## IC_ADG706
designator U?
CMOS, +1.8 V to +5.5 V/ +/-2.5 V, 2.5 OHM, Low-Voltage, 16-Channel Multiplexer
footprint TSOP65P640X110-28N (TSOP, 28-Leads, Body 9.8x4.5mm (max), Pitch 0.65mm, IPC Medium Density)
pins: 1 VDD (power), 2 NC hidden, 3 NC hidden, 4 S16 (io), 5 S15 (io), 6 S14 (io), 7 S13 (io), 8 S12 (io), 9 S11 (io), 10 S10 (io), 11 S9 (io), 12 GND (power), 13 NC hidden, 14 A3 (in), 15 A2 (in), 16 A1 (in), 17 A0 (in), 18 EN (in), 19 S1 (io), 20 S2 (io), 21 S3 (io), 22 S4 (io), 23 S5 (io), 24 S6 (io), 25 S7 (io), 26 S8 (io), 27 VSS (power), 28 D (io)

## IC_ADG714
designator U?
CMOS, Low Voltage  Serially Controlled, Octal SPST Switches
footprint TSOP65P640X120-24N (TSOP, 24-Leads, Body 7.9x4.5mm (max), Pitch 0.65mm, IPC Medium Density)
pins: 1 SCLK, 2 VDD, 3 DIN, 4 GND, 5 S1, 6 D1, 7 S2, 8 D2, 9 S3, 10 D3, 11 S4, 12 D4, 13 D5, 14 S5, 15 D6, 16 S6, 17 D7, 18 S7, 19 D8, 20 S8, 21 VSS, 22 DOUT, 23 ~{RESET}, 24 ~{SYNC}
